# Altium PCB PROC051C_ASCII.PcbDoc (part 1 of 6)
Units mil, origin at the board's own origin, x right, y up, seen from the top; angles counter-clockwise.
Board outline 3304.03 x 2647.77 mil, 6 copper layers (TOP, L2, L3, L4, L5, BOTTOM), stack 55.54 mil thick; 370 components, 273 nets, 1273 pads, 1381 vias.
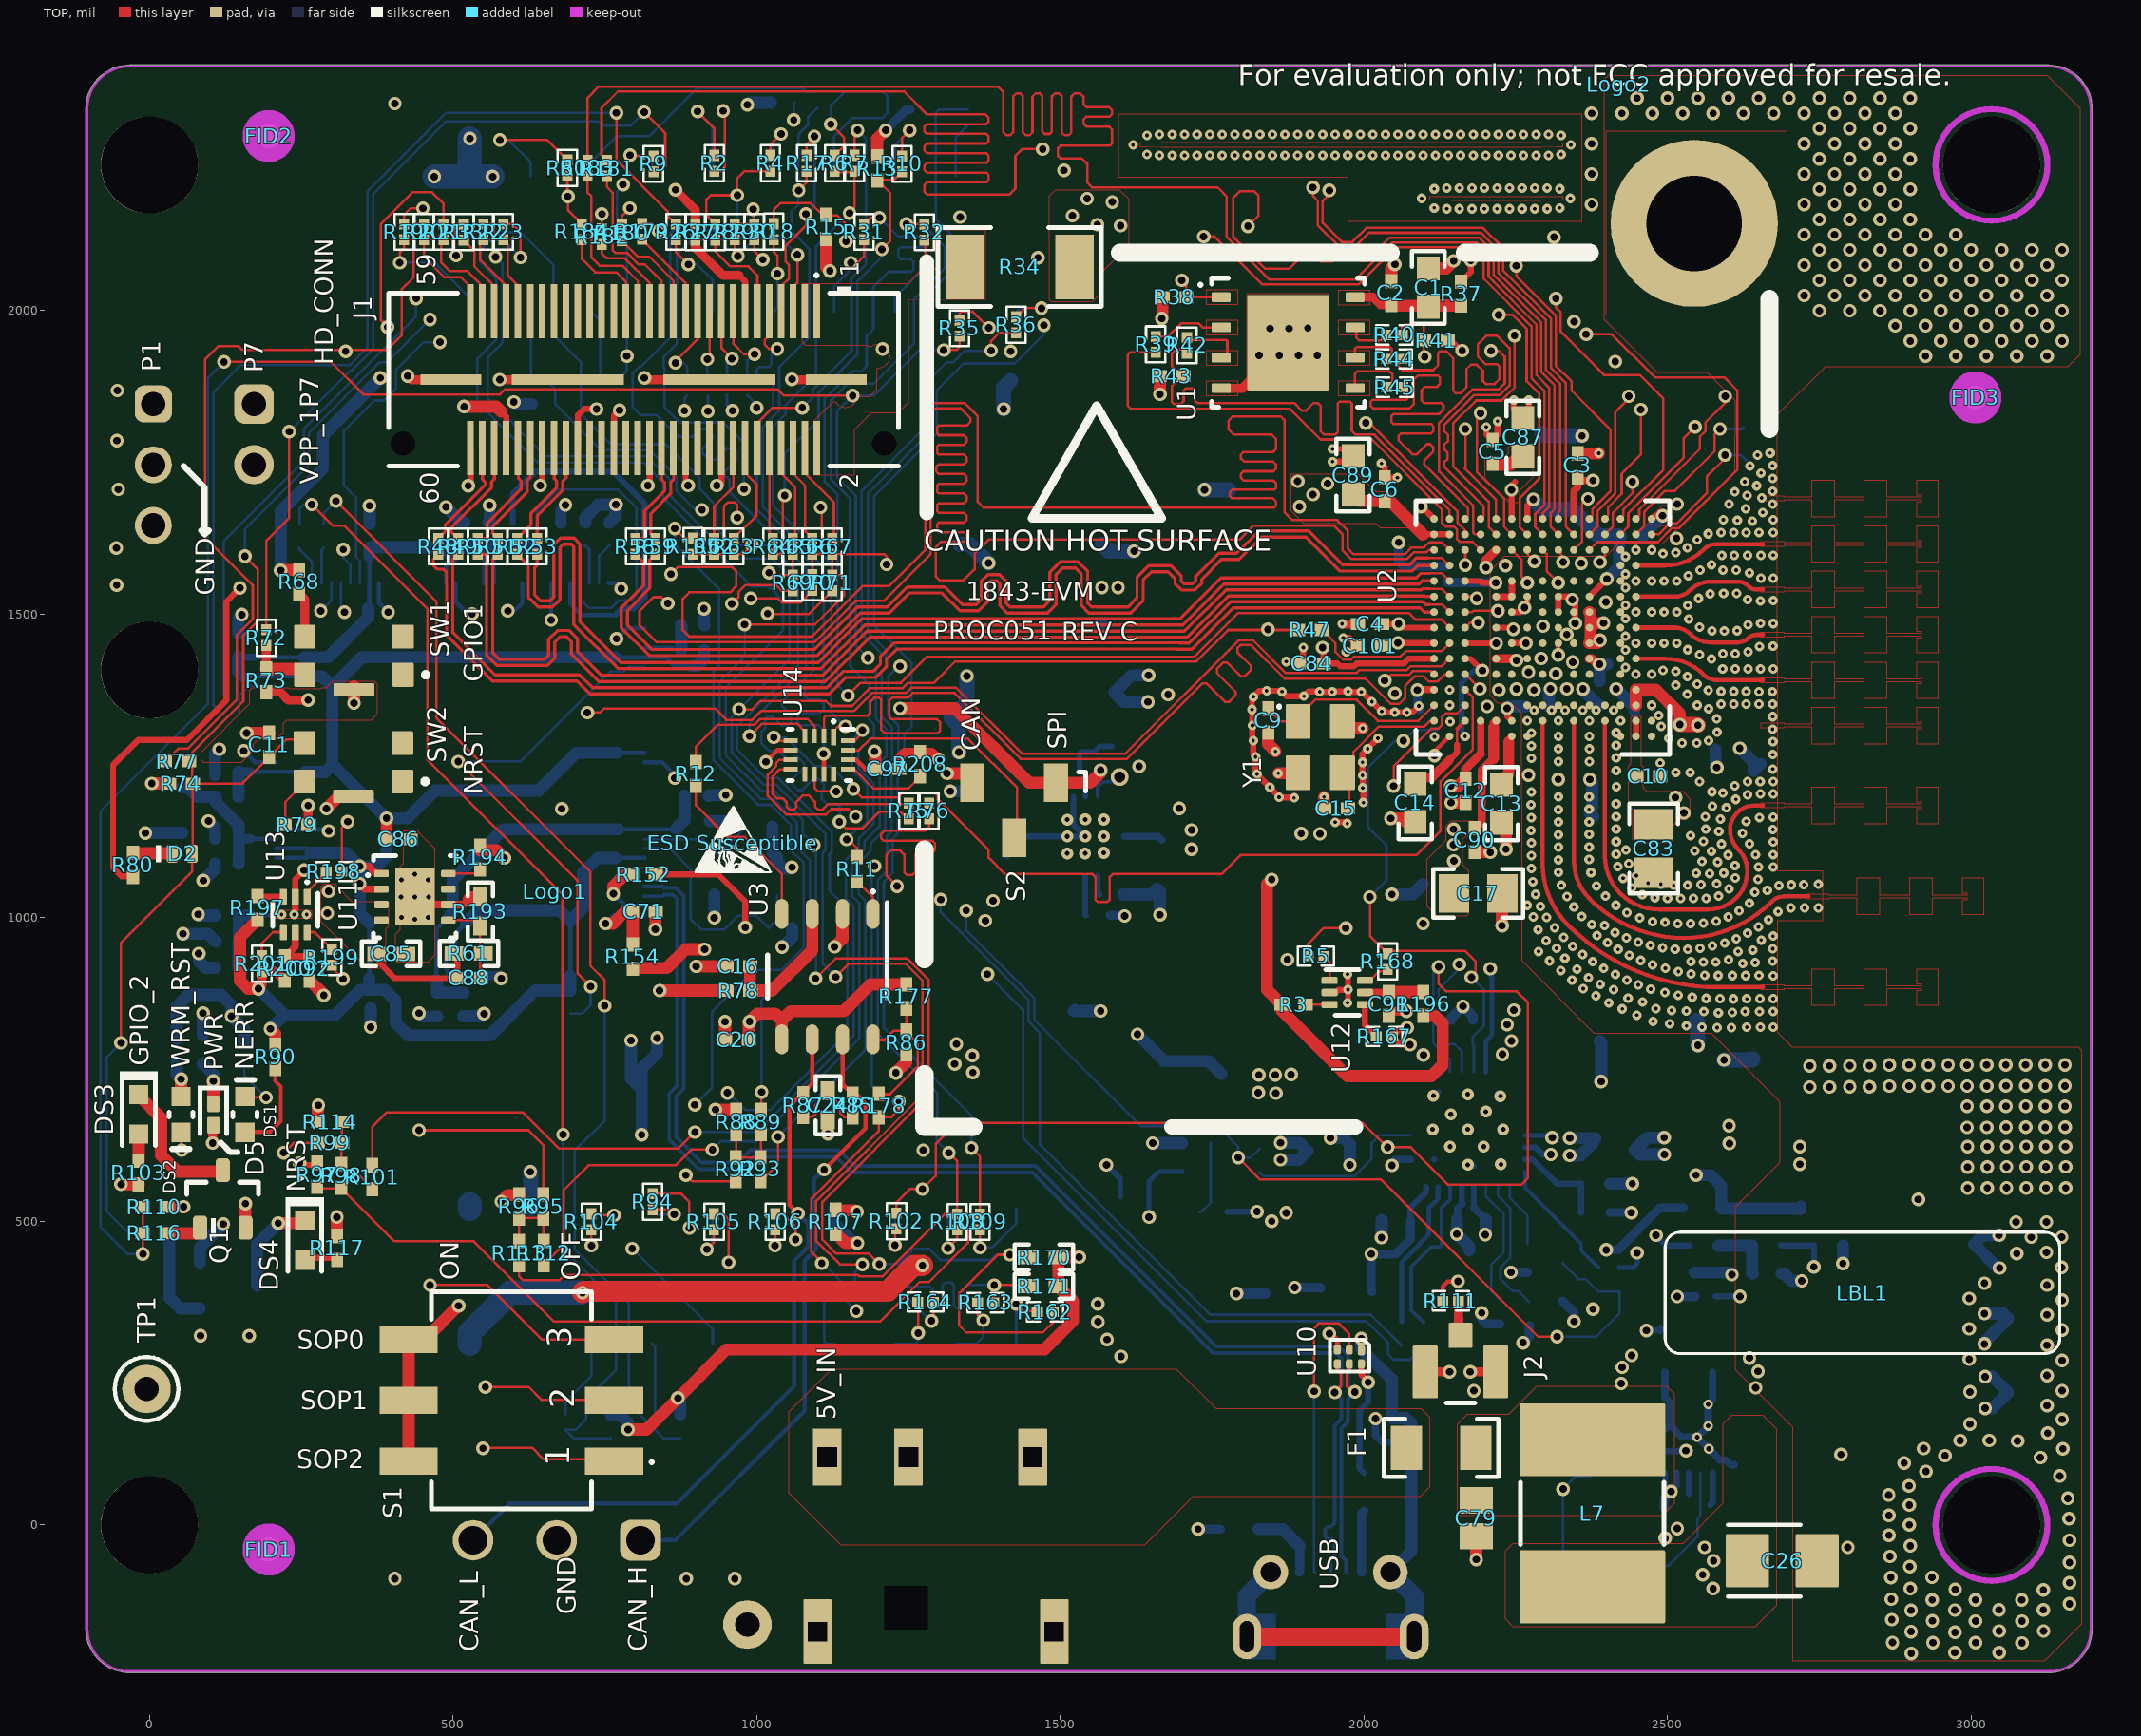
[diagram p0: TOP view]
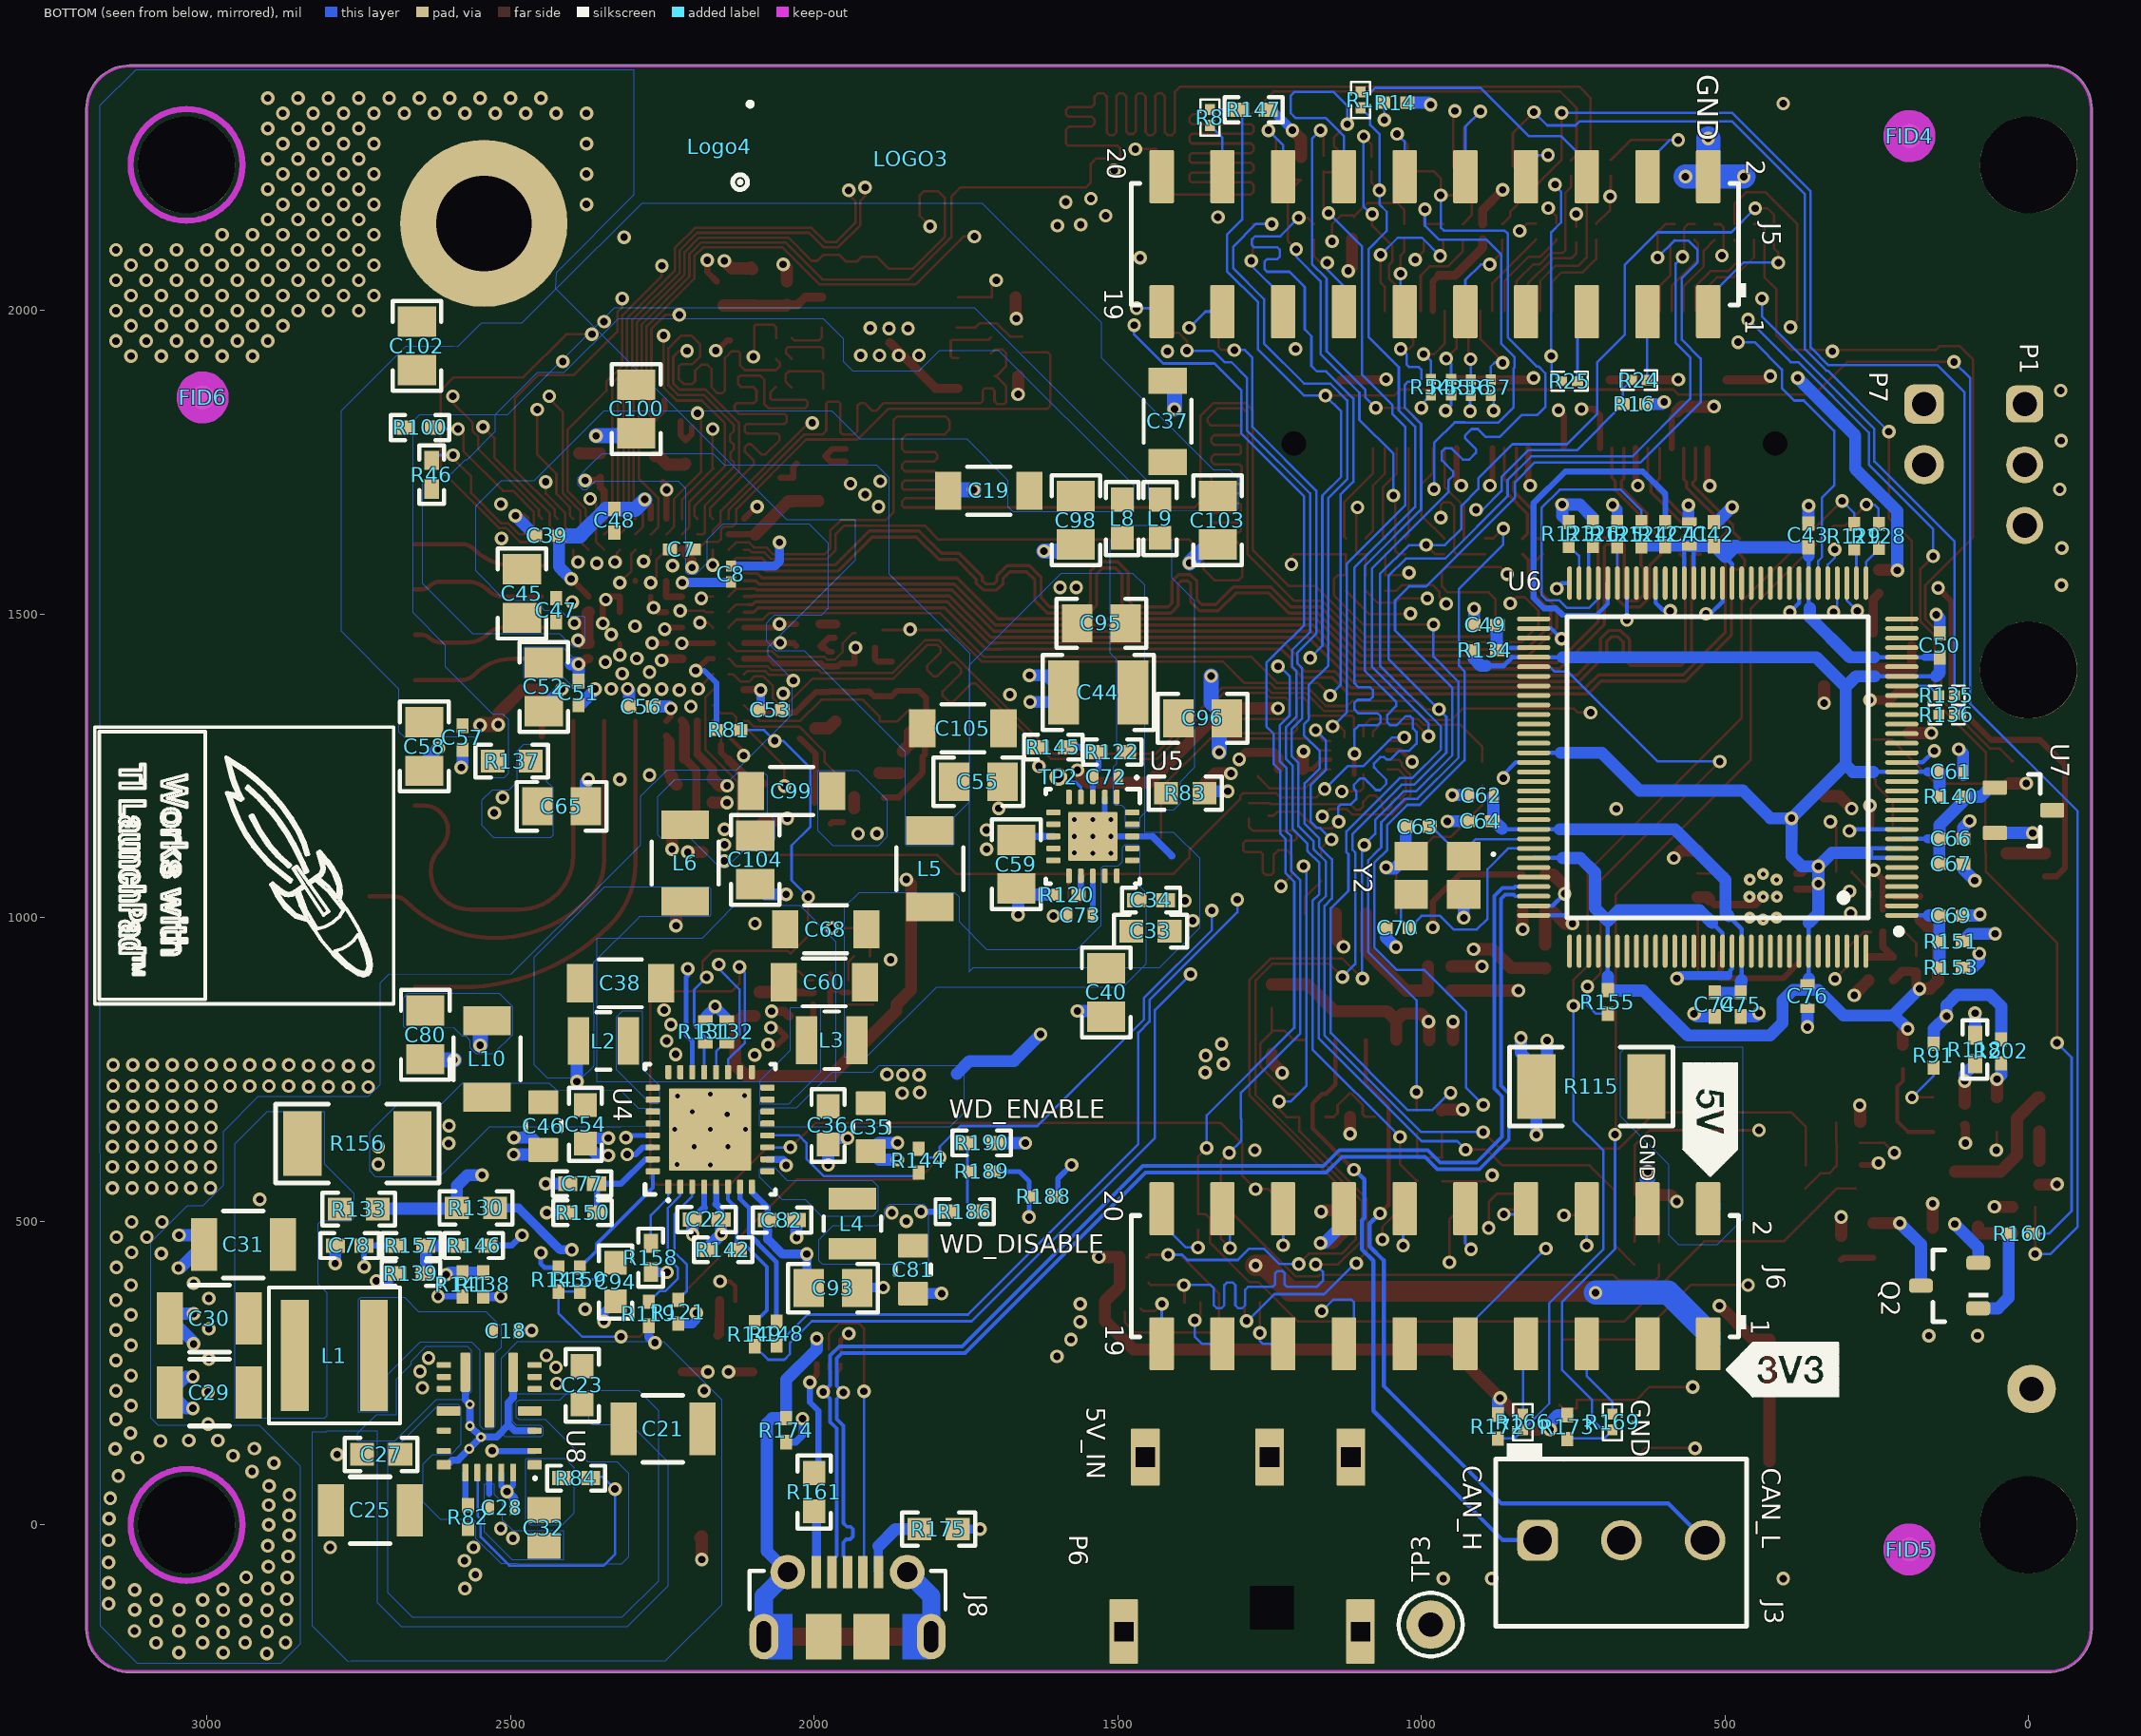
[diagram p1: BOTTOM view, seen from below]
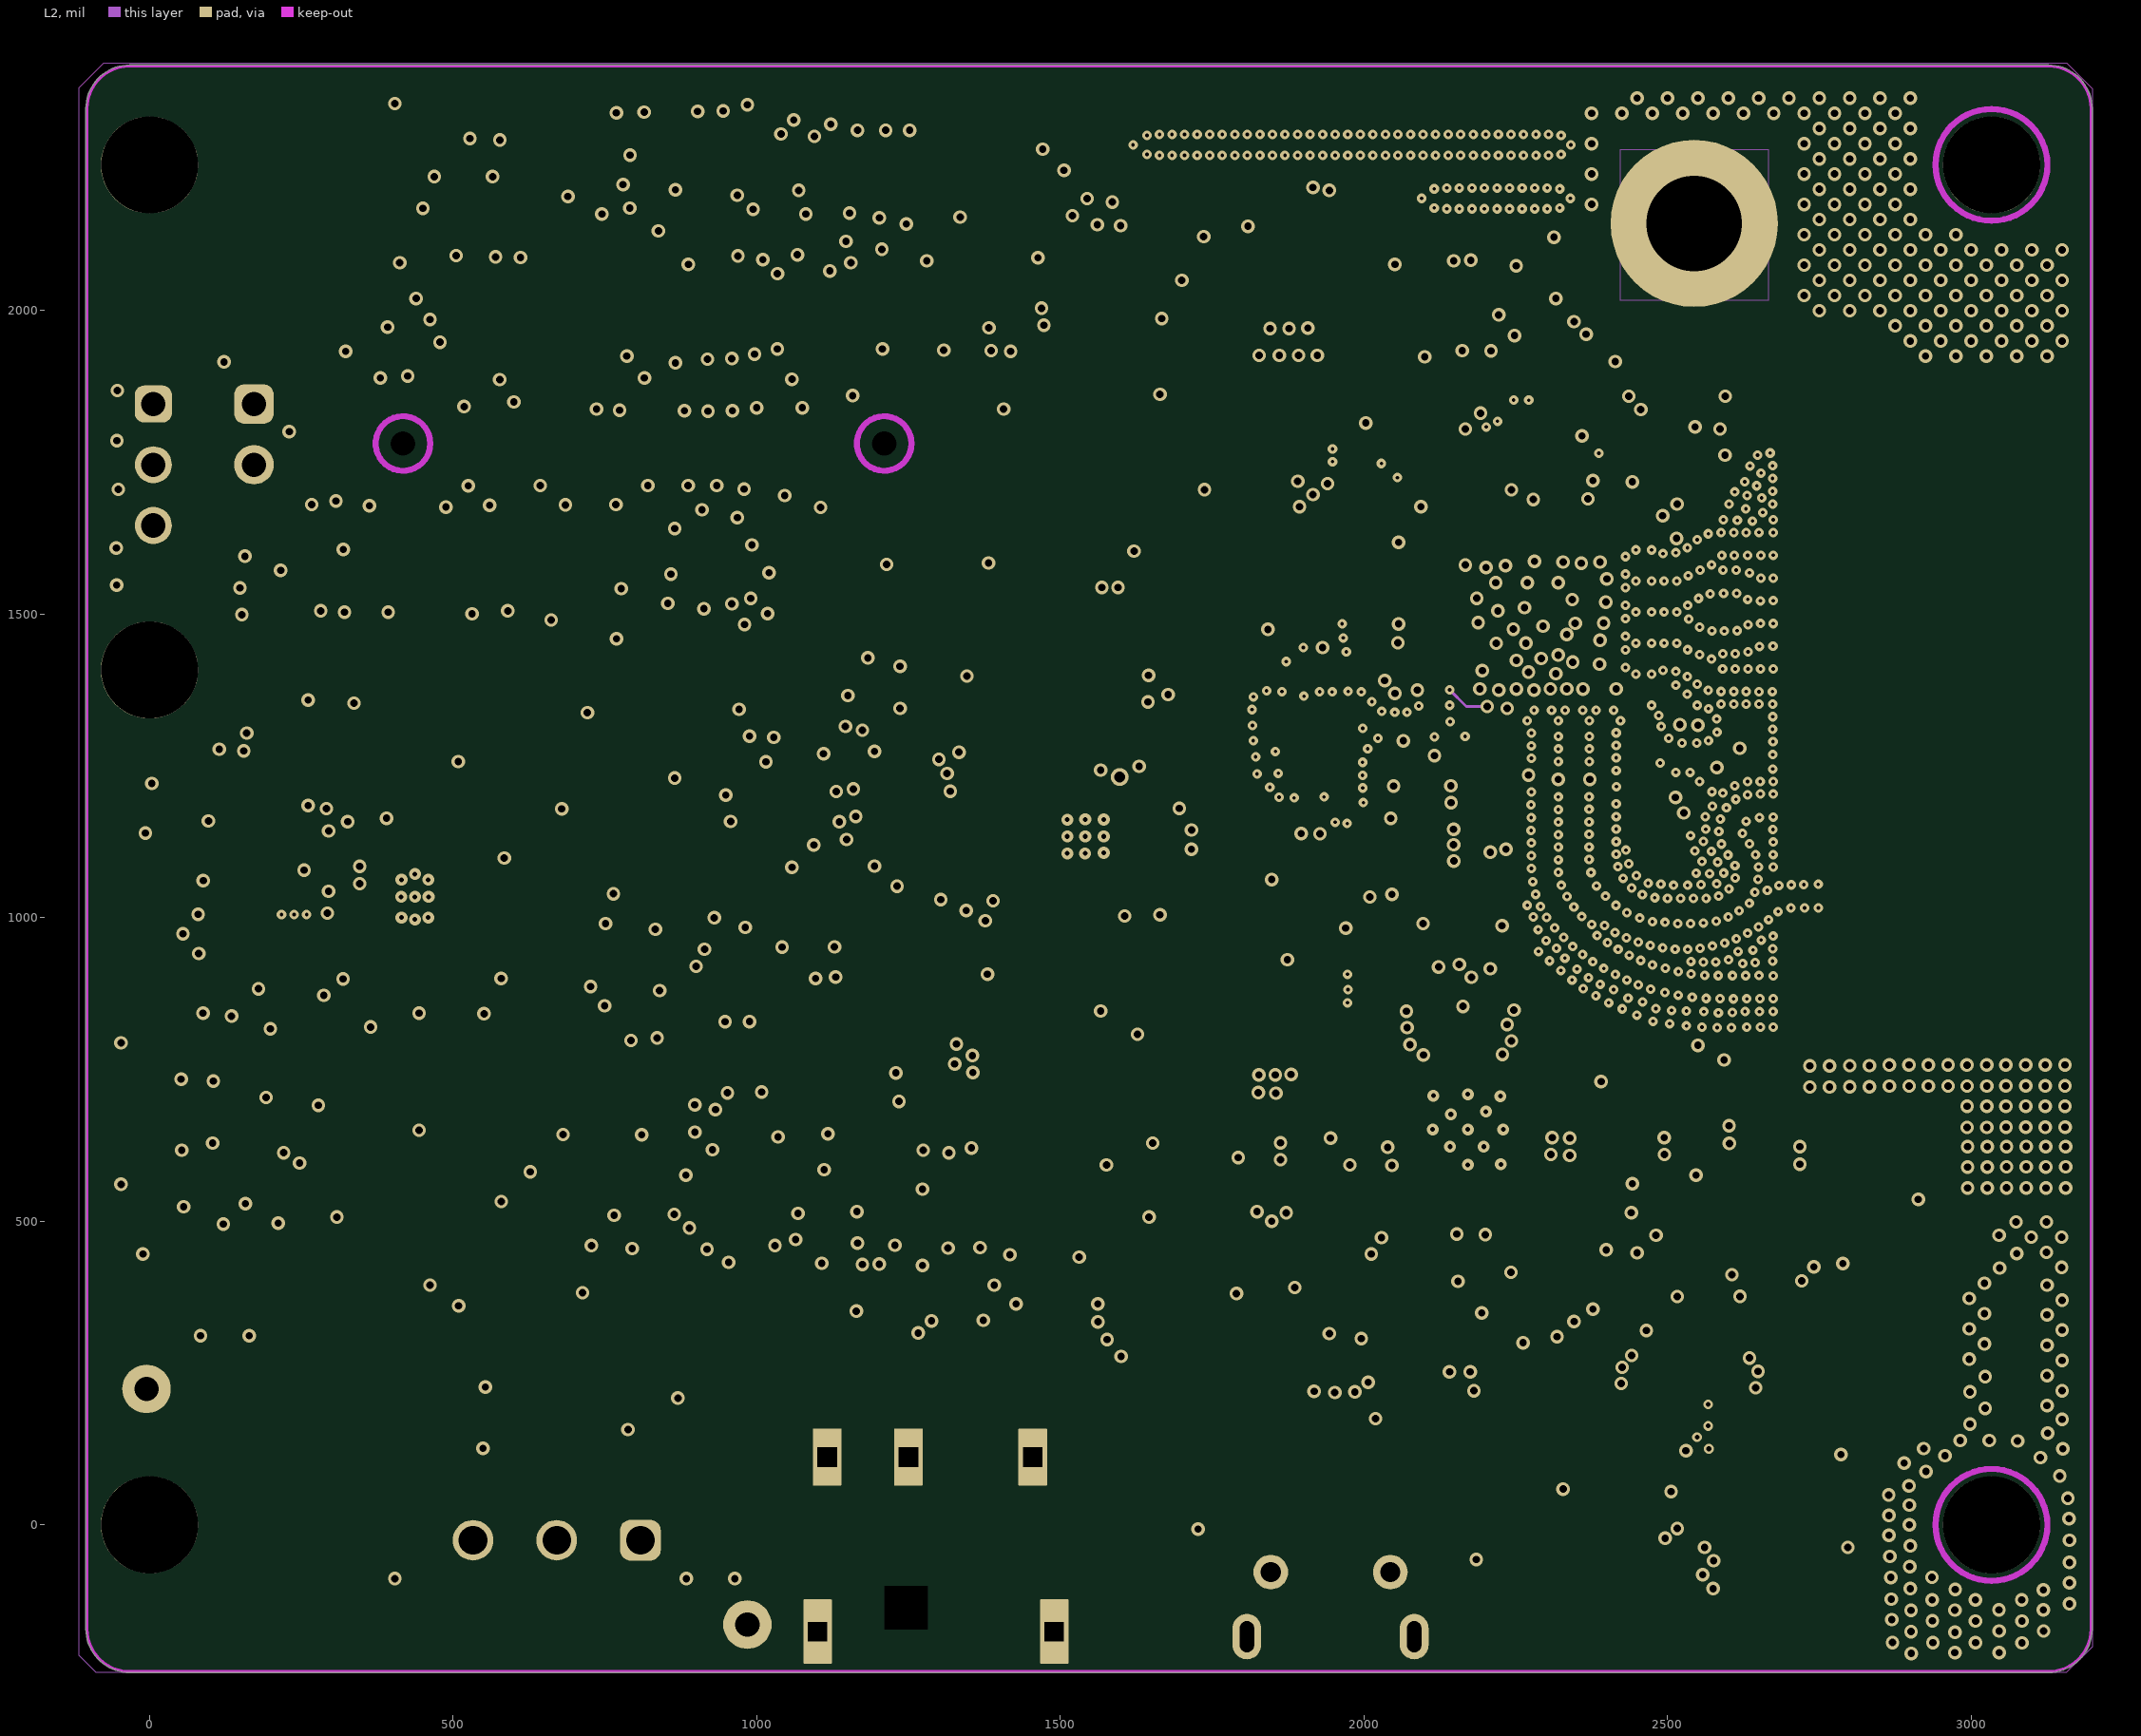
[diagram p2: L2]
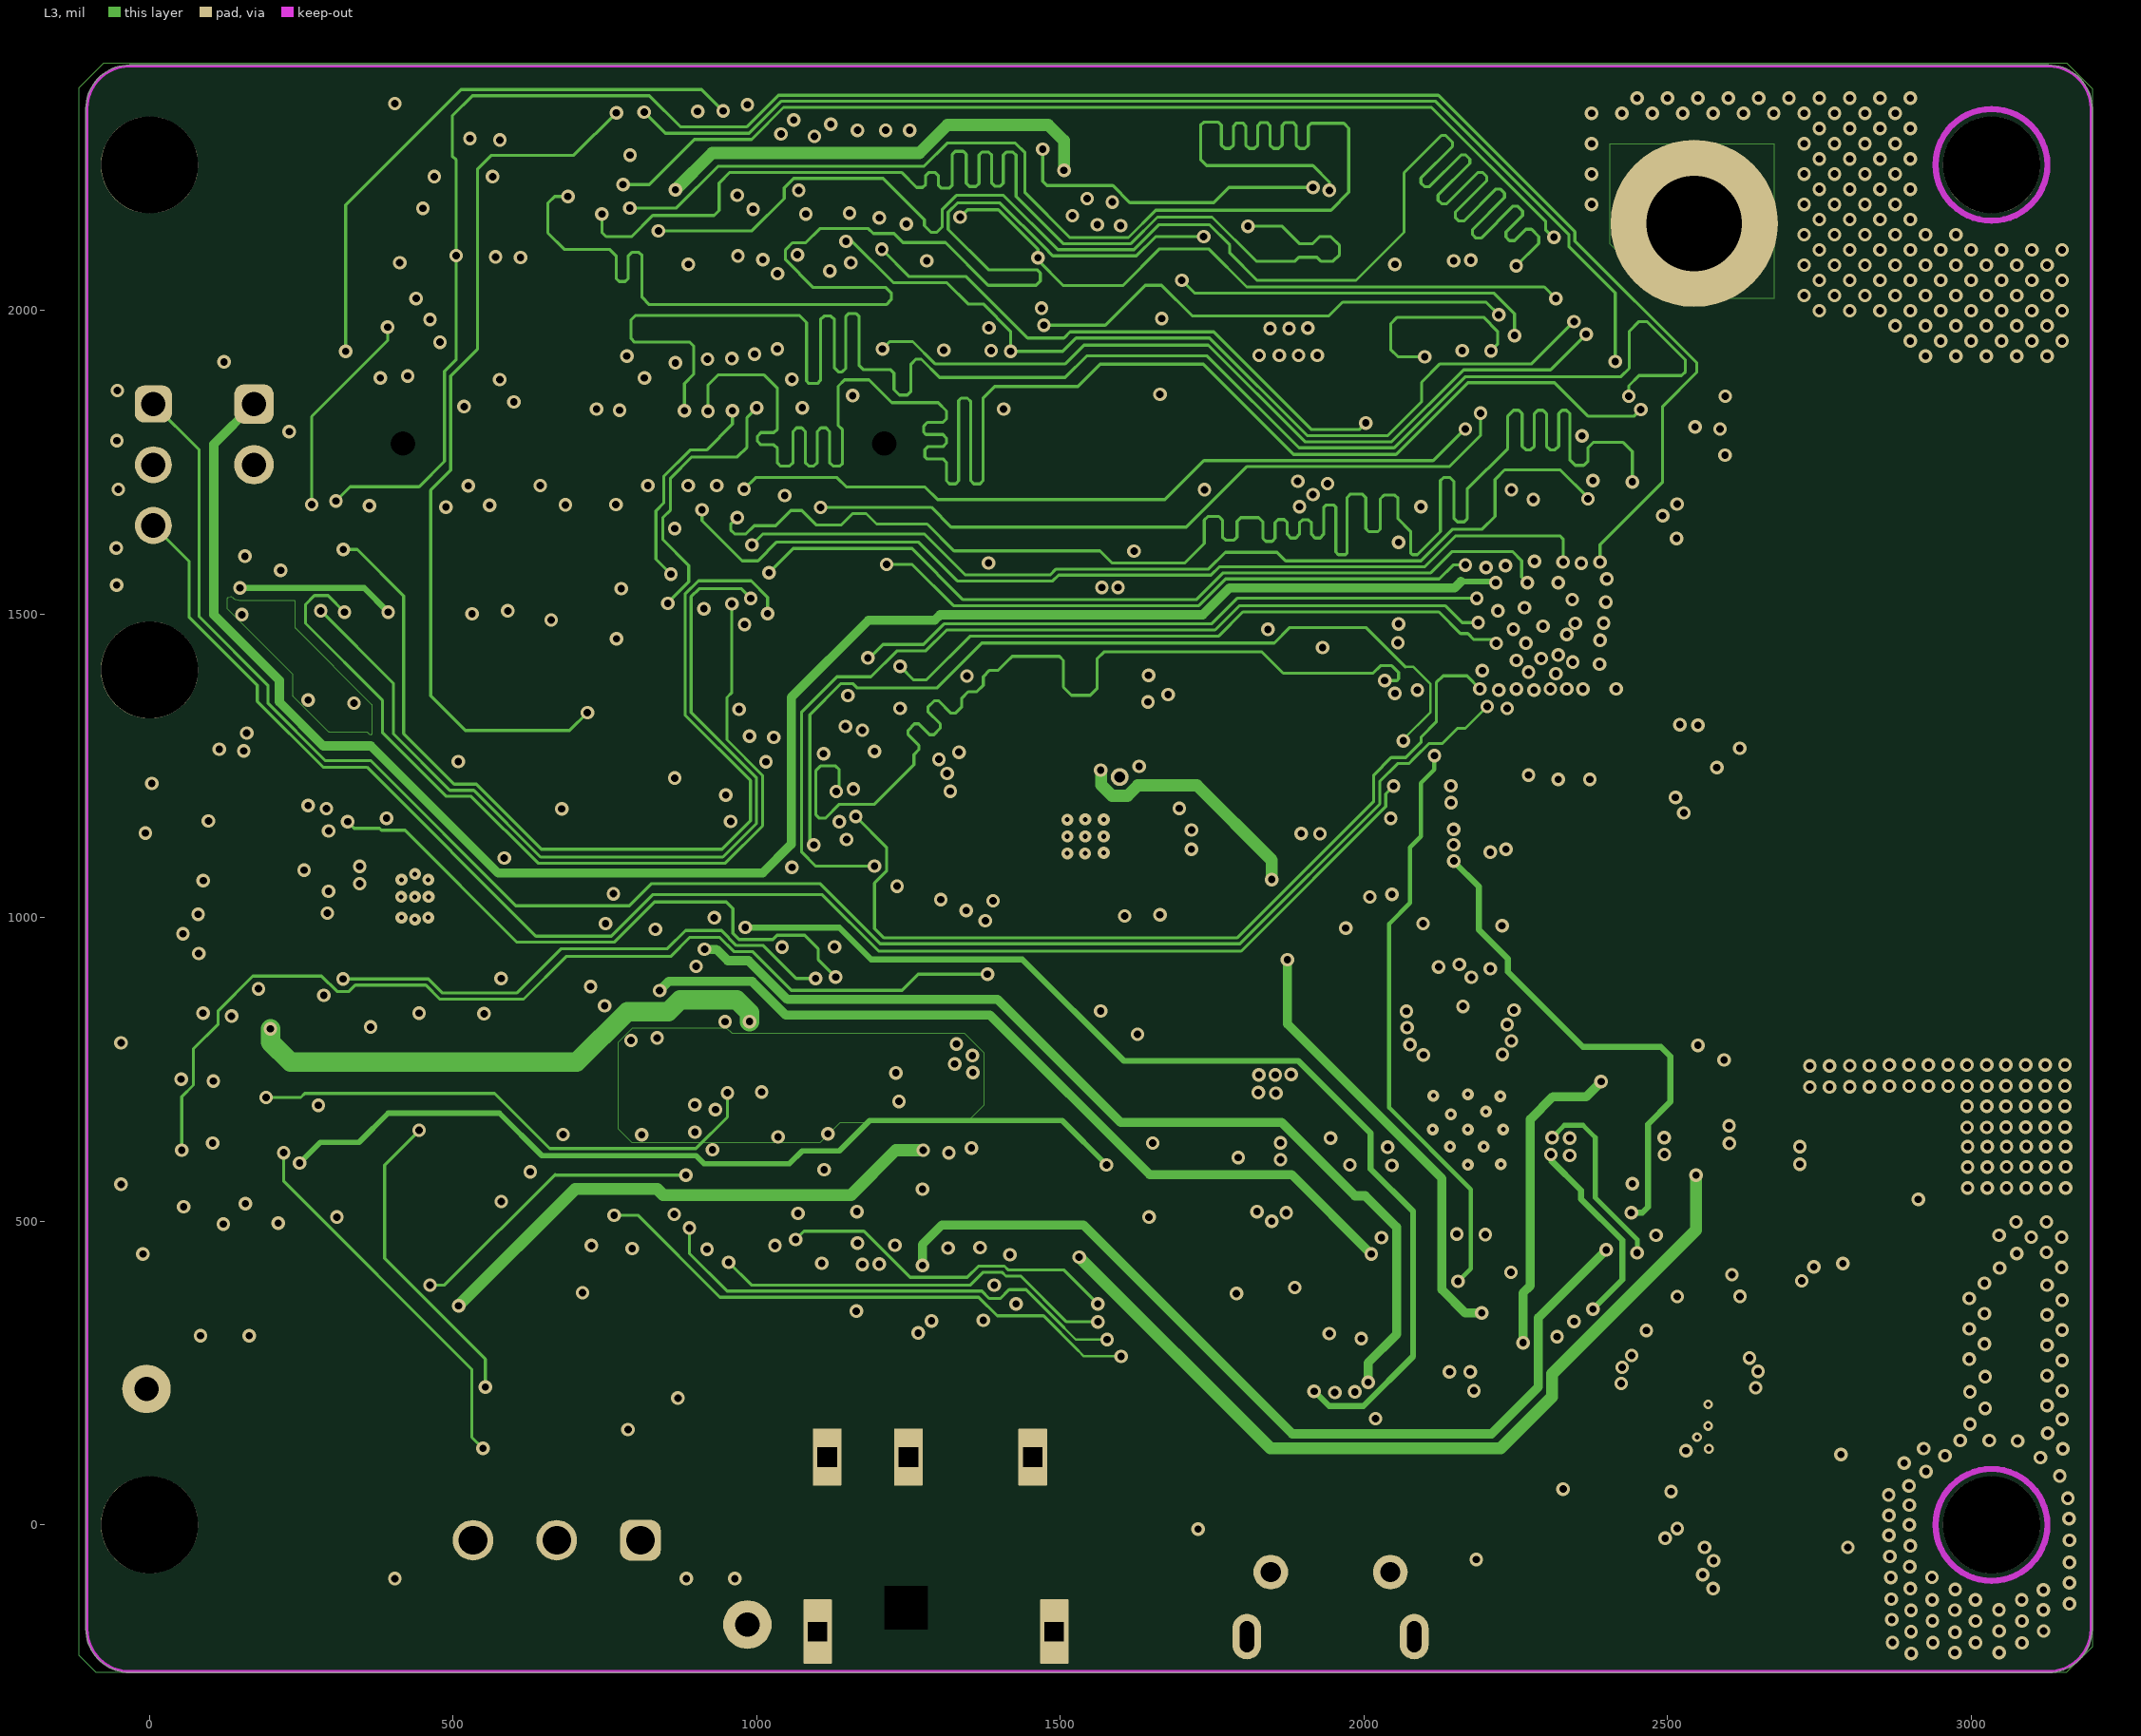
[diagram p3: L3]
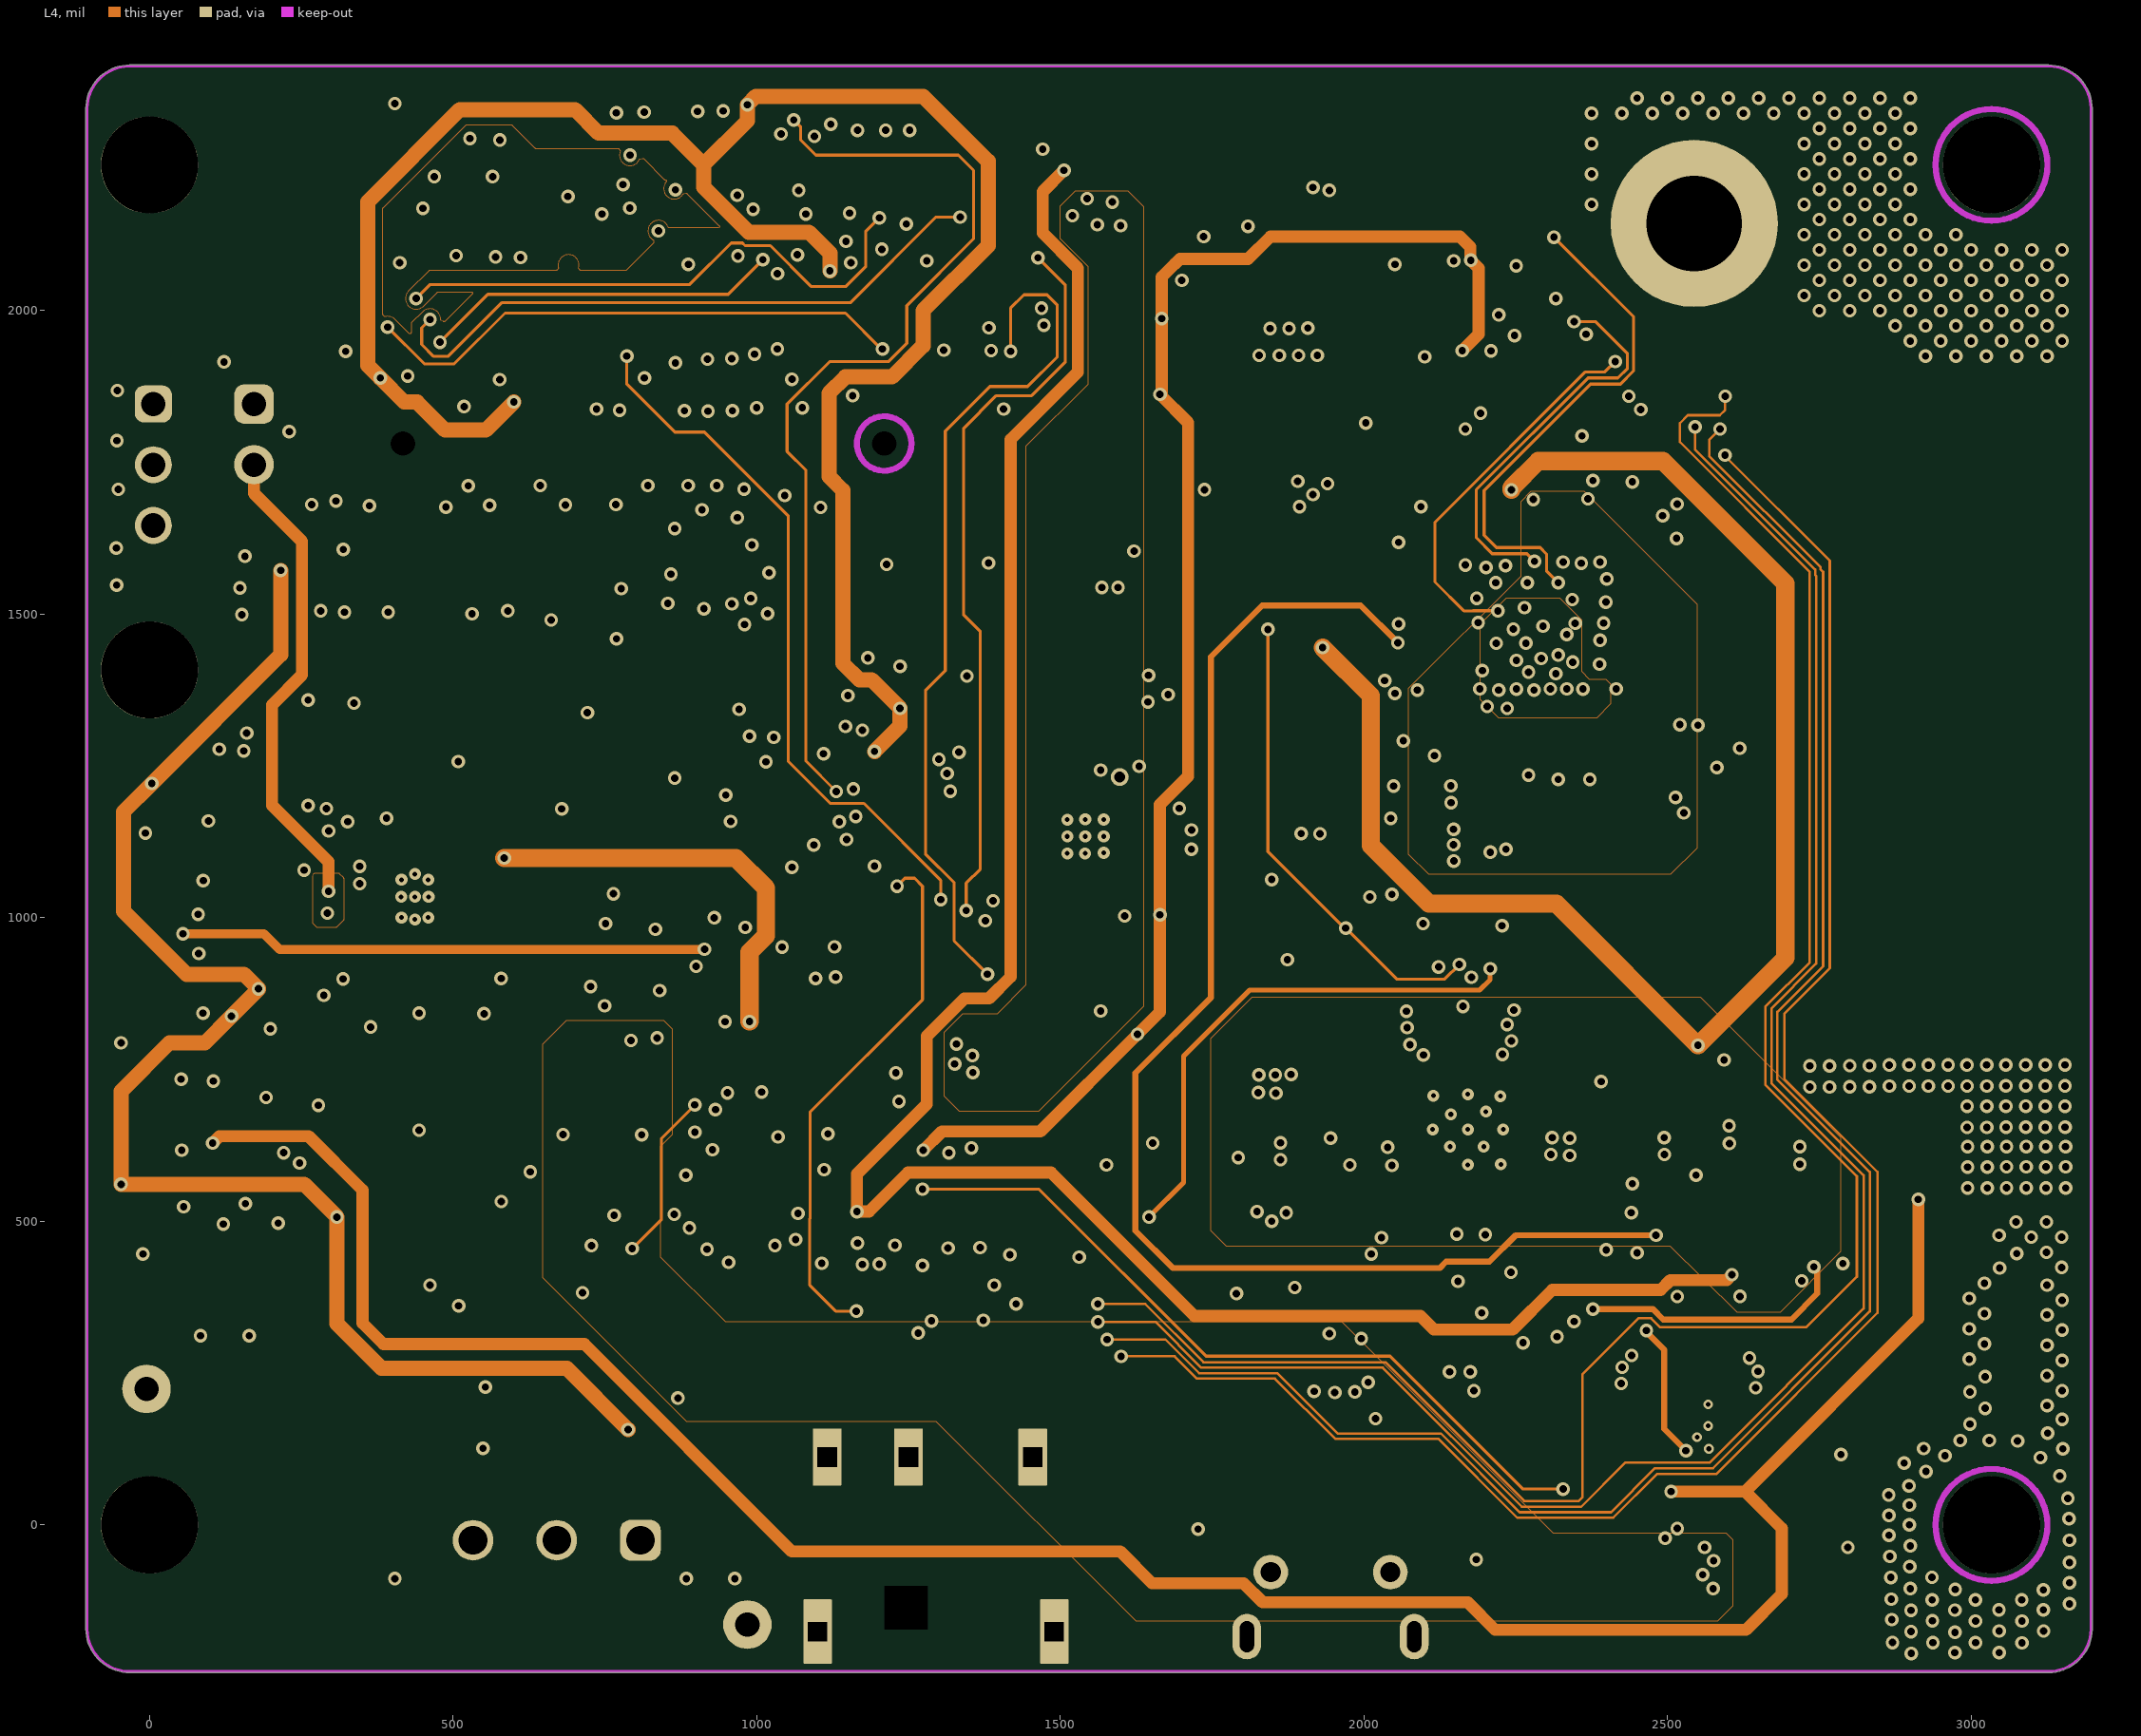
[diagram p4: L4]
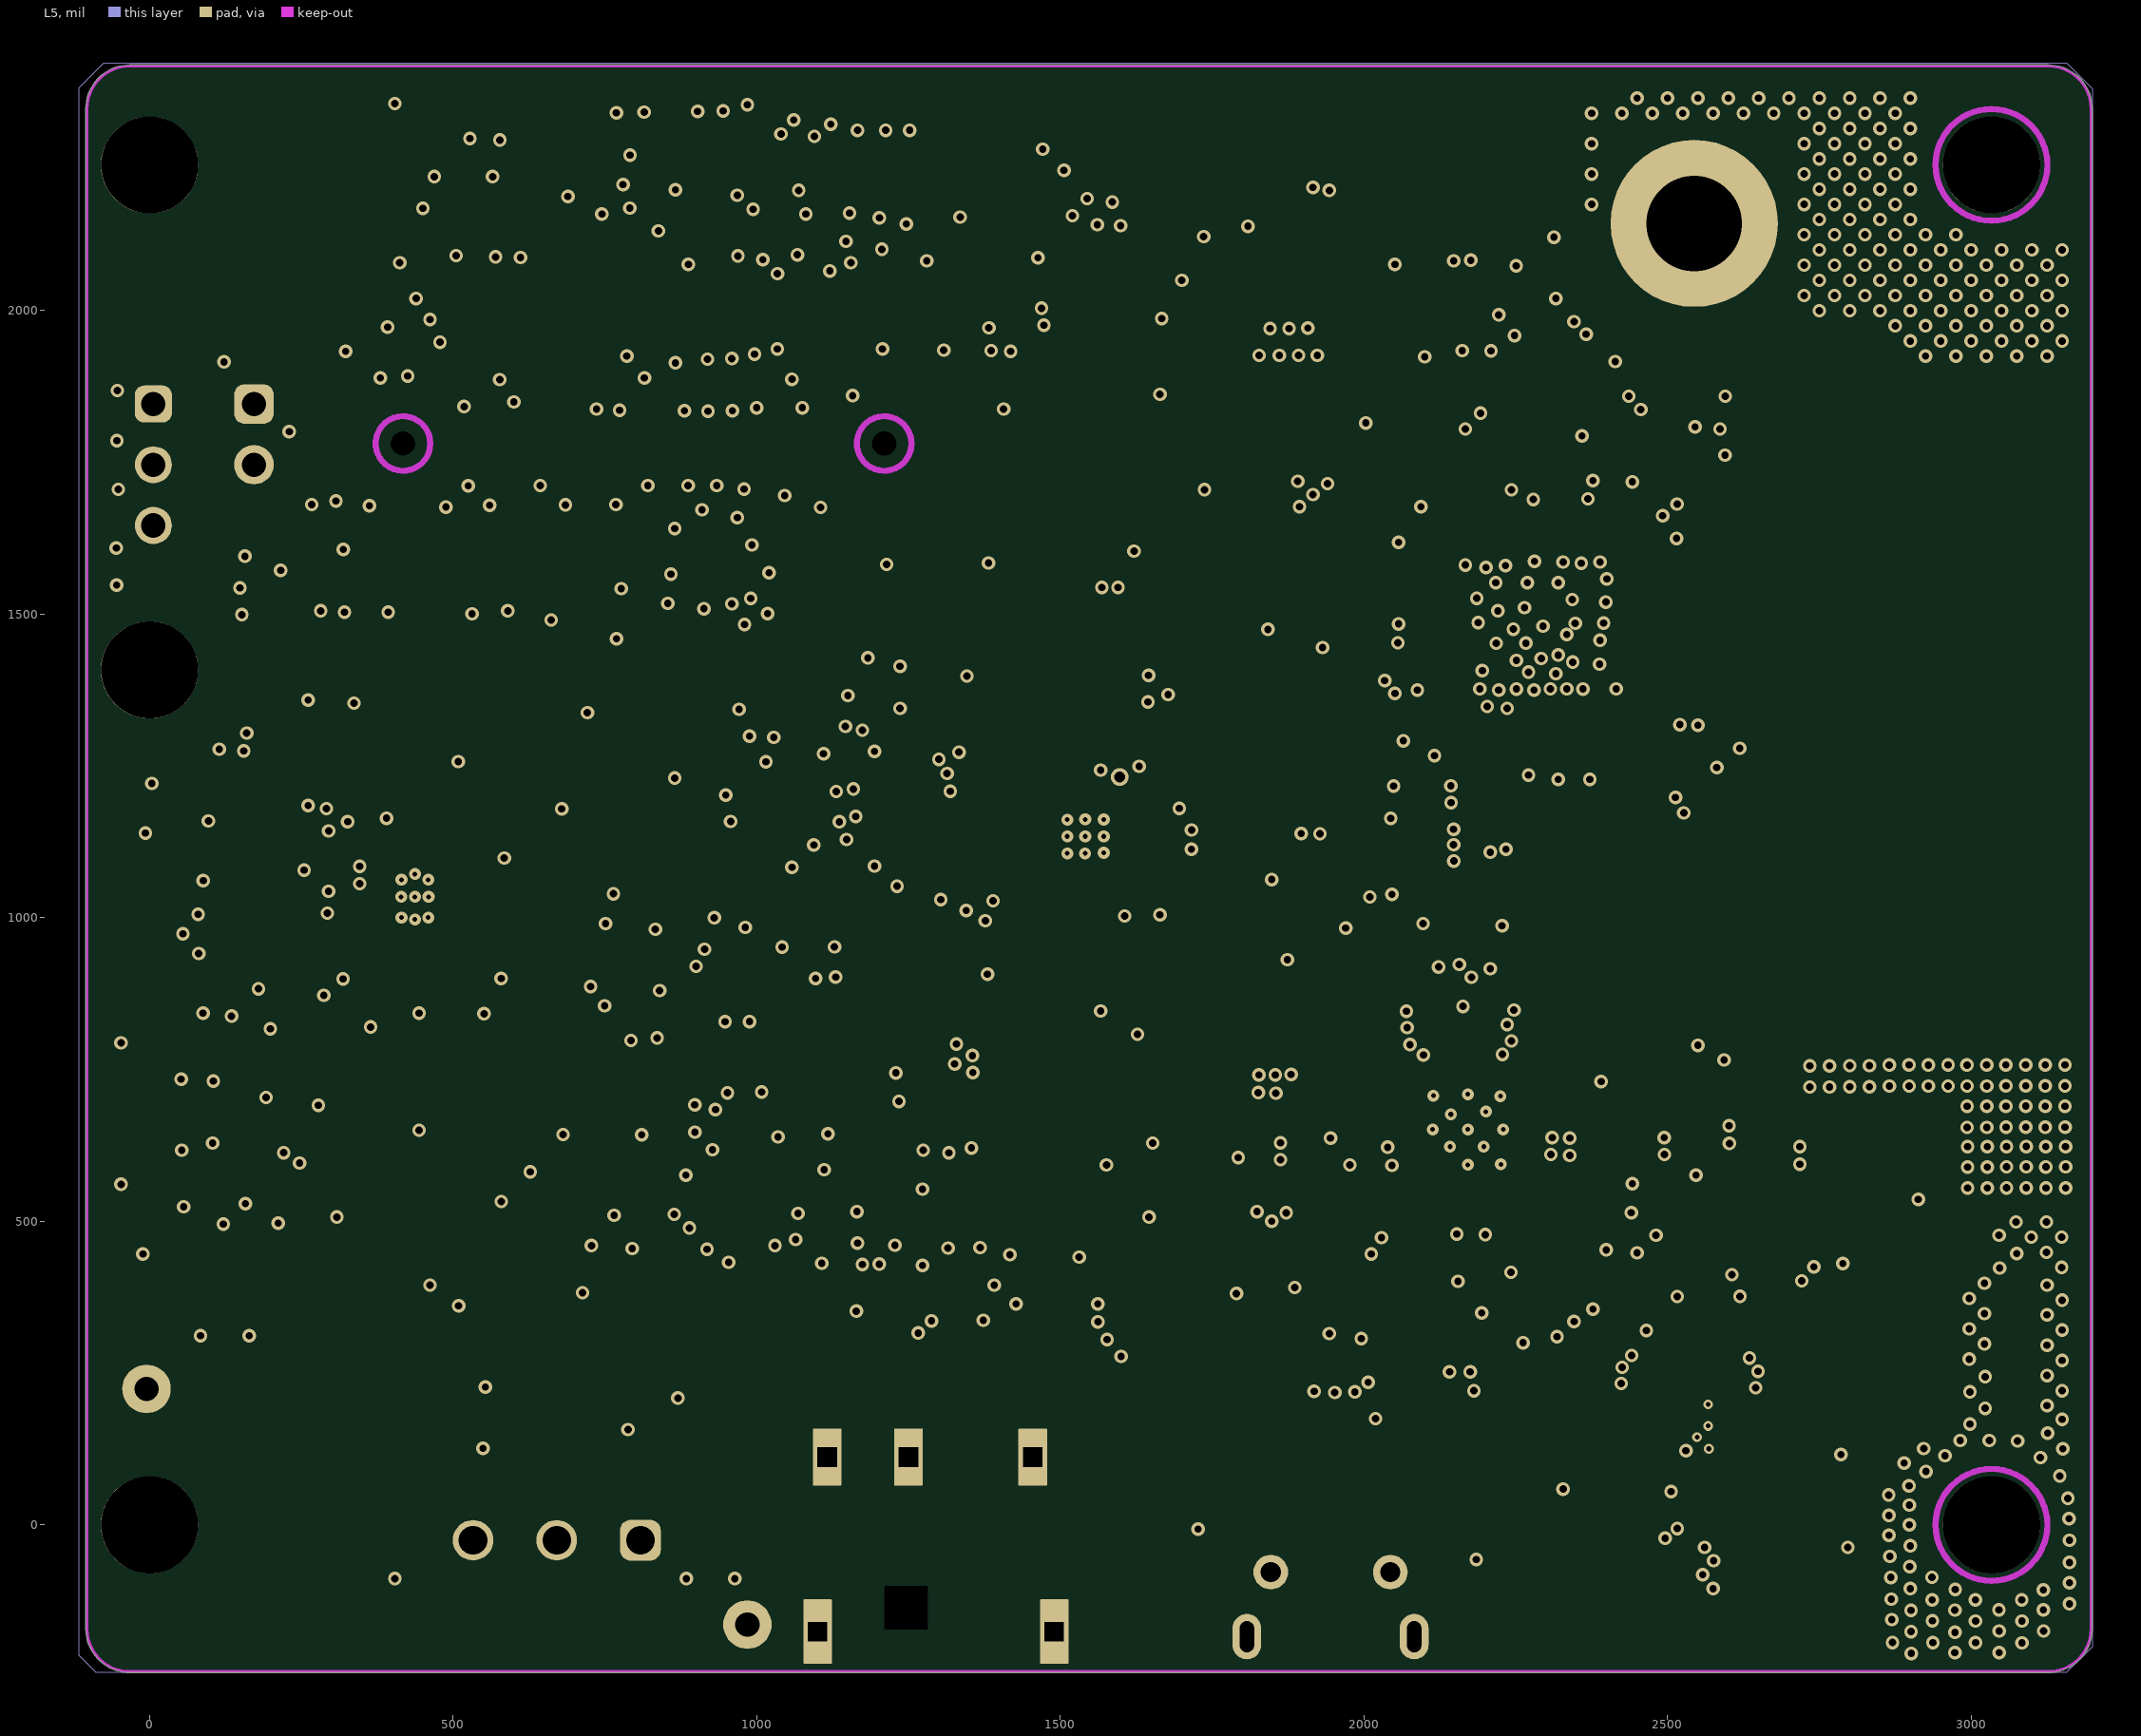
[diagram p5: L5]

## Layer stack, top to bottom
Top Solder: solder mask 0.8, Solder Resist, Dk 3.5
TOP: signal copper 1.6
Dielectric1: core 4, Rogers 4835, Dk 3.66
L2: signal copper 1.2
Dielectric2: prepreg 5.7, 370HR Prepreg 1080, Dk 3.9
L3: signal copper 1.2
Dielectric3: core 28, 370HR Prepreg 1080, Dk 4.36
L4: signal copper 1.2
Dielectric4: prepreg 5.84, 370HR Prepreg 1080, Dk 3.9
L5: signal copper 1.2
Dielectric5: core 4, 370HR Prepreg 1080, Dk 4.26
BOTTOM: signal copper 1.6
Bottom Solder: solder mask 0.8, Solder Resist, Dk 3.5

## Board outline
-104.76,-171.12 cw(c-102.75,-171) -104.76,-171 -104.76,2331.5 cw(c-102.75,2331.5) -104.7,2332 cw(c-102.75,2332.5) -104.76,2332.5 cw(c-32.75,2332.5) -32.75,2404.52 3127.25,2404.52 cw(c3127.25,2332.5) 3199.27,2332.5 3199.27,-172 cw(c3197.25,-172) 3199.26,-172.15 cw(c3127.25,-171.24) 3127.25,-243.26 -32.75,-243.26 cw(c-32.75,-171.24) -104.76,-171.24 cw(c-102.75,-171.24)

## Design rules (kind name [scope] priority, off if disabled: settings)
AssemblyTestPointUsage [All] p0: scope1count=1 scope1_0_kind=Board scope1_0_value=Board scope2count=1 scope2_0_kind=Board scope2_0_value=Board commentlength=0
AssemblyTestpoint [All] p0: scope1count=1 scope1_0_kind=Board scope1_0_value=Board scope2count=1 scope2_0_kind=Board scope2_0_value=Board commentlength=0
Clearance Clearance_L34 [All] p0 off: scope1count=1 scope1_0_kind=Board scope1_0_value=Board scope2count=1 scope2_0_kind=Board scope2_0_value=Board commentlength=60 gap=15 // Protel DXP Scope 1 Expression Was: InLayerClass('L3_L4')
Clearance Clearance_PMIC [All] p0 off: scope1count=1 scope1_0_kind=Board scope1_0_value=Board scope2count=1 scope2_0_kind=Board scope2_0_value=Board commentlength=70 gap=5 // Protel DXP Scope 1 Expression Was: WithinRoom('Copper to PMIC IC')
Clearance Clearance_BTM [All] p0: scope1count=1 scope1_0_kind=Layer scope1_0_value=BOTTOM scope2count=1 scope2_0_kind=Board scope2_0_value=Board commentlength=0 gap=15
Clearance Clearance_L25 [All] p0 off: scope1count=1 scope1_0_kind=Board scope1_0_value=Board scope2count=1 scope2_0_kind=Board scope2_0_value=Board commentlength=60 gap=15 // Protel DXP Scope 1 Expression Was: InLayerClass('L2_L5')
Clearance RX_TX_L34 [All] p0 off: scope1count=1 scope1_0_kind=Board scope1_0_value=Board scope2count=1 scope2_0_kind=NetClass scope2_0_value=RX_TX commentlength=60 gap=10 // Protel DXP Scope 1 Expression Was: InLayerClass('L3_L4')
Clearance COPLANNER [All] p0 off: scope1count=1 scope1_0_kind=Board scope1_0_value=Board scope2count=1 scope2_0_kind=Board scope2_0_value=Board commentlength=59 gap=3 // Protel DXP Scope 1 Expression Was: WithinRoom('COUPLE')
Clearance Clearance_1 [All] p0 off: scope1count=1 scope1_0_kind=Board scope1_0_value=Board scope2count=1 scope2_0_kind=Board scope2_0_value=Board commentlength=69 gap=6.71 // Protel DXP Scope 1 Expression Was: WithinRoom('DUT') OR InPolygon
Clearance Clearance_TOP [All] p0: scope1count=1 scope1_0_kind=Layer scope1_0_value=TOP scope2count=1 scope2_0_kind=Board scope2_0_value=Board commentlength=0 gap=10
Clearance RX_TX_L25 [All] p0 off: scope1count=1 scope1_0_kind=Board scope1_0_value=Board scope2count=1 scope2_0_kind=NetClass scope2_0_value=RX_TX commentlength=60 gap=10 // Protel DXP Scope 1 Expression Was: InLayerClass('L2_L5')
Clearance RX_TX_TOP [All] p0: scope1count=1 scope1_0_kind=Layer scope1_0_value=TOP scope2count=1 scope2_0_kind=NetClass scope2_0_value=RX_TX commentlength=0 gap=10
Clearance same_net_cl_inner [All] p0 off: scope1count=1 scope1_0_kind=Board scope1_0_value=Board scope2count=1 scope2_0_kind=Board scope2_0_value=Board commentlength=61 gap=10 // Protel DXP Scope 1 Expression Was: InLayerClass('layers')
Clearance Clearance_L34 [InLayerClass('L3_L4')] p1: gap=15 ignorepadtopadclearanceinfootprint=FALSE except(0: Arc-Hole Track-Hole SMDPad-Hole THPad-Hole Via-Hole Fill-Hole Poly-Hole Region-Hole Text-Hole; 5: Arc-Track Arc-SMDPad Track-Track Track-SMDPad; 5.9: Via-Via; 6: Arc-Arc Arc-THPad Arc-Via Track-THPad Track-Via SMDPad-SMDPad SMDPad-THPad SMDPad-Via SMDPad-Fill SMDPad-Poly THPad-THPad THPad-Via Via-Fill Via-Poly; 10: THPad-Fill THPad-Poly)
Clearance Clearance_PMIC [WithinRoom('Copper to PMIC IC')] p2: gap=5 ignorepadtopadclearanceinfootprint=FALSE except(0: Arc-Hole Track-Hole SMDPad-Hole THPad-Hole Via-Hole Fill-Hole Poly-Hole Region-Hole Text-Hole; 4: Arc-Track Track-Track; 4.5: Track-Via SMDPad-SMDPad)
Clearance Clearance_BTM [OnLayer('BOTTOM')] p3: gap=15 ignorepadtopadclearanceinfootprint=FALSE except(0: Arc-SMDPad Arc-Hole Track-Hole SMDPad-Hole THPad-Hole Via-Hole Fill-Hole Poly-Hole Region-Hole Text-Hole; 4: Track-SMDPad; 4.5: Arc-Via Track-Via; 5: Arc-Arc Arc-Track Track-Track SMDPad-Via; 6: Arc-THPad Track-THPad SMDPad-SMDPad SMDPad-THPad THPad-THPad THPad-Via; 8: Arc-Fill Arc-Poly Track-Fill Track-Poly Via-Fill Via-Poly; 9: SMDPad-Fill SMDPad-Poly THPad-Fill THPad-Poly; 16.6: Via-Via)
Clearance Clearance_L25 [InLayerClass('L2_L5')] p4: gap=15 ignorepadtopadclearanceinfootprint=FALSE except(0: Arc-Hole Track-Hole SMDPad-Hole THPad-Hole Via-Hole Fill-Hole Poly-Hole Region-Hole Text-Hole; 5: Arc-Track Arc-SMDPad Track-Track Track-SMDPad; 6: Arc-Arc Arc-THPad Arc-Via Track-THPad Track-Via SMDPad-SMDPad SMDPad-THPad SMDPad-Via SMDPad-Fill SMDPad-Poly THPad-THPad THPad-Via Via-Via Via-Fill Via-Poly; 10: THPad-Fill THPad-Poly)
Clearance RX_TX_L34 [InLayerClass('L3_L4') vs InNetClass('RX_TX')] p5: gap=10 ignorepadtopadclearanceinfootprint=FALSE except(0: Arc-Hole Track-Hole SMDPad-Hole THPad-Hole Via-Hole Fill-Hole Poly-Hole Region-Hole Text-Hole; 4.86: Via-Via; 5: Arc-SMDPad Track-SMDPad; 6: Arc-Arc Arc-Track Arc-THPad Arc-Via Track-Track Track-THPad Track-Via SMDPad-SMDPad SMDPad-THPad SMDPad-Via SMDPad-Fill SMDPad-Poly THPad-THPad THPad-Via Via-Fill Via-Poly; 15: Arc-Fill Arc-Poly Track-Poly Fill-Fill Fill-Poly Poly-Poly; 16: Track-Fill)
Clearance COPLANNER [WithinRoom('COUPLE')] p6: gap=3 ignorepadtopadclearanceinfootprint=FALSE except(0: Arc-Hole Track-Hole SMDPad-Hole THPad-Hole Via-Hole Fill-Hole Poly-Hole Region-Hole Text-Hole)
Clearance Clearance_1 [WithinRoom('DUT') OR InPolygon] p7: gap=6.71 ignorepadtopadclearanceinfootprint=FALSE except(0: Arc-Hole Track-Hole SMDPad-Hole THPad-Hole Via-Hole Fill-Hole Poly-Hole Region-Hole Text-Hole; 4: Track-Track Track-SMDPad Track-Via SMDPad-Via; 6.6: Via-Region; 6.72: Arc-Region Arc-Text Track-Region Track-Text SMDPad-Region SMDPad-Text THPad-Region THPad-Text Via-Text Fill-Region Fill-Text Poly-Region Poly-Text Region-Region Region-Text Text-Text; 9: SMDPad-Poly; 10: THPad-Poly)
Clearance Clearance_TOP [OnLayer('TOP')] p8: gap=10 ignorepadtopadclearanceinfootprint=FALSE except(0: Arc-SMDPad Arc-Hole Track-Hole SMDPad-Hole THPad-Hole Via-Hole Fill-Hole Poly-Hole Region-Hole Text-Hole; 4: Arc-Arc Arc-Track Arc-Via Track-Track Track-SMDPad Track-Via; 5: SMDPad-SMDPad SMDPad-THPad SMDPad-Via; 6: Arc-THPad Track-THPad THPad-THPad THPad-Via Via-Fill Via-Poly; 8: Arc-Fill Arc-Poly Track-Fill Track-Poly; 9: SMDPad-Fill SMDPad-Poly THPad-Fill THPad-Poly; 15: Fill-Fill Fill-Poly Poly-Poly; 15.4: Via-Via)
Clearance RX_TX_L25 [InLayerClass('L2_L5') vs InNetClass('RX_TX')] p9: gap=10 ignorepadtopadclearanceinfootprint=FALSE except(0: Arc-Hole Track-Hole SMDPad-Hole THPad-Hole Via-Hole Fill-Hole Poly-Hole Region-Hole Text-Hole; 5: Arc-SMDPad Track-SMDPad; 6: Arc-Arc Arc-Track Arc-THPad Arc-Via Track-Track Track-THPad Track-Via SMDPad-SMDPad SMDPad-THPad SMDPad-Via SMDPad-Fill SMDPad-Poly THPad-THPad THPad-Via Via-Fill Via-Poly; 9.1: Via-Via; 15: Arc-Fill Arc-Poly Track-Fill Track-Poly Fill-Fill Fill-Poly Poly-Poly)
Clearance RX_TX_TOP [OnLayer('TOP') vs InNetClass('RX_TX')] p10: gap=10 ignorepadtopadclearanceinfootprint=FALSE except(0: Arc-Hole Track-Hole SMDPad-Hole THPad-Hole Via-Hole Fill-Hole Poly-Hole Region-Hole Text-Hole; 4: Arc-Track Arc-SMDPad Track-Track Track-SMDPad SMDPad-Via; 6: Arc-THPad Track-THPad SMDPad-SMDPad SMDPad-THPad THPad-THPad THPad-Via THPad-Fill THPad-Poly; 6.7: Arc-Fill Arc-Poly Track-Fill Track-Poly; 6.72: Arc-Via Track-Via Via-Fill Via-Poly; 9: SMDPad-Fill SMDPad-Poly; 15.4: Via-Via)
Clearance same_net_cl_inner [InLayerClass('layers')] p11: gap=10 ignorepadtopadclearanceinfootprint=FALSE except(0: Arc-Hole Track-Hole SMDPad-Hole THPad-Hole Via-Hole Fill-Hole Poly-Hole Region-Hole Text-Hole; 5: Arc-THPad Track-Track Track-SMDPad Track-THPad SMDPad-SMDPad SMDPad-THPad THPad-THPad; 6: Track-Via SMDPad-Via THPad-Via Via-Via Via-Fill Via-Poly; 15: Arc-Fill Arc-Poly Fill-Fill Fill-Poly Poly-Poly)
ComponentClearance [All] p0: scope1count=1 scope1_0_kind=Board scope1_0_value=Board scope2count=1 scope2_0_kind=Board scope2_0_value=Board commentlength=0 gap=10 collisioncheckmode=3
DiffPairsRouting Diff_100ohm [All] p0 off: scope1count=1 scope1_0_kind=Board scope1_0_value=Board scope2count=1 scope2_0_kind=Board scope2_0_value=Board commentlength=73 // Protel DXP Scope 1 Expression Was: InDifferentialPairClass('100_OHM')
DiffPairsRouting Diff_90ohm [All] p0 off: scope1count=1 scope1_0_kind=Board scope1_0_value=Board scope2count=1 scope2_0_kind=Board scope2_0_value=Board commentlength=72 // Protel DXP Scope 1 Expression Was: InDifferentialPairClass('90_OHM')
DiffPairsRouting [All] p0: scope1count=1 scope1_0_kind=Board scope1_0_value=Board scope2count=1 scope2_0_kind=Board scope2_0_value=Board commentlength=0
DiffPairsRouting Diff_100ohm [InDifferentialPairClass('100_OHM')] p1: maxlimit=5 minlimit=5 mostfreqgap=5 toplayer_minwidth=4 toplayer_maxwidth=5.2 toplayer_prefwidth=5.2 midlayer1_minwidth=4 midlayer1_maxwidth=5.2 midlayer1_prefwidth=5.2 midlayer2_minwidth=4 midlayer2_maxwidth=5.2 midlayer2_prefwidth=5.2 midlayer3_minwidth=4 midlayer3_maxwidth=5.2 midlayer3_prefwidth=5.2 midlayer4_minwidth=4 midlayer4_maxwidth=5.2 midlayer4_prefwidth=5.2 bottomlayer_minwidth=4 bottomlayer_maxwidth=5.2 bottomlayer_prefwidth=5.2 maxuncoupledlength=500
DiffPairsRouting Diff_90ohm [InDifferentialPairClass('90_OHM')] p2: maxlimit=5 minlimit=5 mostfreqgap=5 toplayer_minwidth=5.2 toplayer_maxwidth=5.2 toplayer_prefwidth=5.2 midlayer1_minwidth=6 midlayer1_maxwidth=6 midlayer1_prefwidth=6 midlayer2_minwidth=6 midlayer2_maxwidth=6 midlayer2_prefwidth=6 midlayer3_minwidth=6 midlayer3_maxwidth=6 midlayer3_prefwidth=6 midlayer4_minwidth=6 midlayer4_maxwidth=6 midlayer4_prefwidth=6 bottomlayer_minwidth=6 bottomlayer_maxwidth=6 bottomlayer_prefwidth=6 maxuncoupledlength=500
DiffPairsRouting [All] p3: maxlimit=5 minlimit=4 mostfreqgap=5 toplayer_minwidth=4 toplayer_maxwidth=6 toplayer_prefwidth=5.2 midlayer1_minwidth=4 midlayer1_maxwidth=6 midlayer1_prefwidth=5.2 midlayer2_minwidth=4 midlayer2_maxwidth=6 midlayer2_prefwidth=5.2 midlayer3_minwidth=4 midlayer3_maxwidth=6 midlayer3_prefwidth=5.2 midlayer4_minwidth=4 midlayer4_maxwidth=6 midlayer4_prefwidth=5.2 bottomlayer_minwidth=4 bottomlayer_maxwidth=6 bottomlayer_prefwidth=5.2 maxuncoupledlength=500
FabricationTestPointUsage [All] p0: scope1count=1 scope1_0_kind=Board scope1_0_value=Board scope2count=1 scope2_0_kind=Board scope2_0_value=Board commentlength=0 valid=0 allowmultiple=FALSE
FabricationTestpoint [All] p0: scope1count=1 scope1_0_kind=Board scope1_0_value=Board scope2count=1 scope2_0_kind=Board scope2_0_value=Board commentlength=0 side=3 testpointundercomponent=TRUE minsize=40 maxsize=100 preferedsize=60 minholesize=0 maxholesize=40 preferedholesize=32 testpointgrid=1
FanoutControl Fanout_BGA [All] p0 off: scope1count=1 scope1_0_kind=Board scope1_0_value=Board scope2count=1 scope2_0_kind=Board scope2_0_value=Board commentlength=69 // Protel DXP Scope 1 Expression Was: IsBGA   Fanout_BGA (Default Rule)
FanoutControl Fanout_LCC [All] p0 off: scope1count=1 scope1_0_kind=Board scope1_0_value=Board scope2count=1 scope2_0_kind=Board scope2_0_value=Board commentlength=69 // Protel DXP Scope 1 Expression Was: IsLCC   Fanout_LCC (Default Rule)
FanoutControl Fanout_SOIC [All] p0 off: scope1count=1 scope1_0_kind=Board scope1_0_value=Board scope2count=1 scope2_0_kind=Board scope2_0_value=Board commentlength=71 // Protel DXP Scope 1 Expression Was: IsSOIC   Fanout_SOIC (Default Rule)
FanoutControl Fanout_Small [All] p0 off: scope1count=1 scope1_0_kind=Board scope1_0_value=Board scope2count=1 scope2_0_kind=Board scope2_0_value=Board commentlength=84 // Protel DXP Scope 1 Expression Was: (CompPinCount < 5)   Fanout_Small (Default Rule)
FanoutControl Fanout_Default [All] p0: scope1count=1 scope1_0_kind=Board scope1_0_value=Board scope2count=1 scope2_0_kind=Board scope2_0_value=Board commentlength=30 // Fanout_Default (Default Rule)
Height [All] p0: scope1count=1 scope1_0_kind=Board scope1_0_value=Board scope2count=1 scope2_0_kind=Board scope2_0_value=Board commentlength=0
HoleSize [All] p0: scope1count=1 scope1_0_kind=Board scope1_0_value=Board scope2count=1 scope2_0_kind=Board scope2_0_value=Board commentlength=0 absolutevalues=TRUE maxlimit=200 minlimit=5.9 maxpercent=80.000 minpercent=20.000
HoleSize [All] p1: absolutevalues=TRUE maxlimit=200 minlimit=5.9 maxpercent=80.000 minpercent=20.000
HoleToHoleClearance [All] p0: scope1count=1 scope1_0_kind=Board scope1_0_value=Board scope2count=1 scope2_0_kind=Board scope2_0_value=Board commentlength=0
LayerPairs [All] p0: scope1count=1 scope1_0_kind=Board scope1_0_value=Board scope2count=1 scope2_0_kind=Board scope2_0_value=Board commentlength=0 enforce=TRUE
Length DIFF_2 [All] p0 off: scope1count=1 scope1_0_kind=Board scope1_0_value=Board scope2count=1 scope2_0_kind=Board scope2_0_value=Board commentlength=72 maxlimit=2250 minlimit=2200 // Protel DXP Scope 1 Expression Was: InDifferentialPairClass('90_OHM')
Length DIFF_1 [All] p0 off: scope1count=1 scope1_0_kind=Board scope1_0_value=Board scope2count=1 scope2_0_kind=Board scope2_0_value=Board commentlength=73 maxlimit=1910 minlimit=1880 // Protel DXP Scope 1 Expression Was: InDifferentialPairClass('100_OHM')
Length QSPI [All] p0 off: scope1count=1 scope1_0_kind=Board scope1_0_value=Board scope2count=1 scope2_0_kind=Board scope2_0_value=Board commentlength=61 maxlimit=1160 minlimit=950 // Protel DXP Scope 1 Expression Was: InxSignalClass('QSPI')
Length Length_2 [All] p0: scope1count=1 scope1_0_kind=Board scope1_0_value=Board scope2count=1 scope2_0_kind=Board scope2_0_value=Board commentlength=0 maxlimit=20000 minlimit=0
Length DIFF_2 [InDifferentialPairClass('90_OHM')] p1: maxlimit=2250 minlimit=2200
Length DIFF_1 [InDifferentialPairClass('100_OHM')] p2: maxlimit=1910 minlimit=1880
Length QSPI [InxSignalClass('QSPI')] p3: maxlimit=1160 minlimit=950
Length Length_2 [All] p4: maxlimit=20000 minlimit=0
MatchedLengths SPI_2_NEW [All] p0 off: scope1count=1 scope1_0_kind=Board scope1_0_value=Board scope2count=1 scope2_0_kind=Board scope2_0_value=Board commentlength=61 tolerance=500 amplitude=200 gap=20 style=90-Degree // Protel DXP Scope 1 Expression Was: InxSignalClass('SPI2')
MatchedLengths LVDS_1 [All] p0 off: scope1count=1 scope1_0_kind=Board scope1_0_value=Board scope2count=1 scope2_0_kind=Board scope2_0_value=Board commentlength=61 tolerance=5 amplitude=200 gap=20 style=90-Degree // Protel DXP Scope 1 Expression Was: InxSignalClass('LVDS')
MatchedLengths DATA-0-7 [All] p0 off: scope1count=1 scope1_0_kind=Board scope1_0_value=Board scope2count=1 scope2_0_kind=Board scope2_0_value=Board commentlength=65 tolerance=200 amplitude=200 gap=20 style=90-Degree // Protel DXP Scope 1 Expression Was: InxSignalClass('DATA_0_7')
MatchedLengths MUX_TO_J1 [All] p0 off: scope1count=1 scope1_0_kind=Board scope1_0_value=Board scope2count=1 scope2_0_kind=Board scope2_0_value=Board commentlength=66 tolerance=250 amplitude=200 gap=20 style=90-Degree // Protel DXP Scope 1 Expression Was: InxSignalClass('mux_to_j1')
MatchedLengths MUX_J5 [All] p0 off: scope1count=1 scope1_0_kind=Board scope1_0_value=Board scope2count=1 scope2_0_kind=Board scope2_0_value=Board commentlength=66 tolerance=250 amplitude=200 gap=20 style=90-Degree // Protel DXP Scope 1 Expression Was: InxSignalClass('mux_to_j5')
MatchedLengths U2_MUX [All] p0 off: scope1count=1 scope1_0_kind=Board scope1_0_value=Board scope2count=1 scope2_0_kind=Board scope2_0_value=Board commentlength=66 tolerance=250 amplitude=200 gap=20 style=90-Degree // Protel DXP Scope 1 Expression Was: InxSignalClass('U2_TO_MUX')
MatchedLengths SPI_2_NEW [InxSignalClass('SPI2')] p1: tolerance=500 checknetsindiffpair=FALSE checkdiffpairvsdiffpair=TRUE checkxsignals=TRUE checkothers=TRUE
MatchedLengths LVDS_1 [InxSignalClass('LVDS')] p2: tolerance=5 checknetsindiffpair=FALSE checkdiffpairvsdiffpair=TRUE checkxsignals=TRUE checkothers=TRUE
MatchedLengths DATA-0-7 [InxSignalClass('DATA_0_7')] p3: tolerance=200 checknetsindiffpair=FALSE checkdiffpairvsdiffpair=TRUE checkxsignals=TRUE checkothers=TRUE
MatchedLengths MUX_TO_J1 [InxSignalClass('mux_to_j1')] p4: tolerance=250 checknetsindiffpair=FALSE checkdiffpairvsdiffpair=TRUE checkxsignals=TRUE checkothers=TRUE
MatchedLengths MUX_J5 [InxSignalClass('mux_to_j5')] p5: tolerance=250 checknetsindiffpair=FALSE checkdiffpairvsdiffpair=TRUE checkxsignals=TRUE checkothers=TRUE
MatchedLengths U2_MUX [InxSignalClass('U2_TO_MUX')] p6: tolerance=250 checknetsindiffpair=FALSE checkdiffpairvsdiffpair=TRUE checkxsignals=TRUE checkothers=TRUE
MinimumAnnularRing [All] p0: scope1count=1 scope1_0_kind=Board scope1_0_value=Board scope2count=1 scope2_0_kind=Board scope2_0_value=Board commentlength=0 minimumring=3.9
MinimumAnnularRing [All] p1: minimumring=3.9
MinimumSolderMaskSliver [All] p0: scope1count=1 scope1_0_kind=Board scope1_0_value=Board scope2count=1 scope2_0_kind=Board scope2_0_value=Board commentlength=0
MinimumSolderMaskSliver [All] p1: minsoldermaskwidth=4
NetAntennae [All] p0: scope1count=1 scope1_0_kind=Board scope1_0_value=Board scope2count=1 scope2_0_kind=Board scope2_0_value=Board commentlength=0
PasteMaskExpansion [All] p0: scope1count=1 scope1_0_kind=Board scope1_0_value=Board scope2count=1 scope2_0_kind=Board scope2_0_value=Board commentlength=0 expansion=0
PlaneClearance [All] p0: scope1count=1 scope1_0_kind=Board scope1_0_value=Board scope2count=1 scope2_0_kind=Board scope2_0_value=Board commentlength=0 clearance=20
PlaneConnect [All] p0: scope1count=1 scope1_0_kind=Board scope1_0_value=Board scope2count=1 scope2_0_kind=Board scope2_0_value=Board commentlength=0 planeconnectstyle=Direct reliefexpansion=20 reliefentries=4 reliefconductorwidth=10 reliefairgap=10
PlaneConnect [All] p1: planeconnectstyle=Direct reliefexpansion=20 reliefentries=4 reliefconductorwidth=10 reliefairgap=10
PolygonConnect [All] p0: scope1count=1 scope1_0_kind=Board scope1_0_value=Board scope2count=1 scope2_0_kind=Board scope2_0_value=Board commentlength=0 connectstyle=Direct reliefconductorwidth=10 reliefentries=4 polygonreliefangle="90 Angle"
PolygonConnect [All] p1: connectstyle=Direct reliefconductorwidth=10 reliefentries=4 polygonreliefangle="90 Angle" airgapwidth=10
RoomDefinition DUT [All] p0: scope1count=1 scope1_0_kind=ComponentClass scope1_0_value=DUT scope2count=1 scope2_0_kind=Board scope2_0_value=Board commentlength=0 region_x1=30930000 region_y1=24735000 region_x2=41000000 region_y2=36225000 confinementstyle=ConfineIn
RoomDefinition COUPLE [All] p0 off: scope1count=1 scope1_0_kind=Board scope1_0_value=Board scope2count=1 scope2_0_kind=Board scope2_0_value=Board commentlength=63 region_x1=25869300 region_y1=40166500 region_x2=33615700 region_y2=42076600 confinementstyle=ConfineOut // Protel DXP Scope 1 Expression Was: WithinRoom('CO_PLANNER')
RoomDefinition DUT [InComponentClass('DUT')] p1: confinementstyle=ConfineIn formatcopy=TRUE lockcomponents=FALSE outline 2143,1735.5 2154,1746.5 3074,1746.5 3100,1720.5 3100,619.5 3078,597.5 2381,597.5 2306,672.5 2306,1214.5 2269,1251.5 2156,1251.5 2093,1314.5 2093,1712.5 2116,1735.5
RoomDefinition COUPLE [WithinRoom('CO_PLANNER')] p2: confinementstyle=ConfineOut formatcopy=TRUE lockcomponents=FALSE outline 1592.53,2331.66 1593.27,2330.92 2361.57,2330.92 2361.57,2143.54 2358.68,2140.65 1974.97,2140.65 1965.68,2149.94 1965.68,2214.31 1595.03,2214.31 1586.93,2222.41
RoutingCorners [All] p0: scope1count=1 scope1_0_kind=Board scope1_0_value=Board scope2count=1 scope2_0_kind=Board scope2_0_value=Board commentlength=0 cornerstyle=45-Degree minsetback=100 maxsetback=100
RoutingLayers [All] p0: scope1count=1 scope1_0_kind=Board scope1_0_value=Board scope2count=1 scope2_0_kind=Board scope2_0_value=Board commentlength=0 top layer=Automatic mid layer 1=Automatic mid layer 2=Automatic mid layer 3=Automatic mid layer 4=Automatic bottom layer=Automatic
RoutingPriority [All] p0: scope1count=1 scope1_0_kind=Board scope1_0_value=Board scope2count=1 scope2_0_kind=Board scope2_0_value=Board commentlength=0
RoutingTopology [All] p0: scope1count=1 scope1_0_kind=Board scope1_0_value=Board scope2count=1 scope2_0_kind=Board scope2_0_value=Board commentlength=0 topology=Shortest
RoutingVias [All] p0: scope1count=1 scope1_0_kind=Board scope1_0_value=Board scope2count=1 scope2_0_kind=Board scope2_0_value=Board commentlength=0 holewidth=12.2 width=22.4 viastyle="Through Hole" minholewidth=5.9 minwidth=13 maxholewidth=24 maxwidth=50
RoutingVias [All] p1: holewidth=12.2 width=22.4 viastyle="Through Hole" minholewidth=5.9 minwidth=13 maxholewidth=24 maxwidth=50
ShortCircuit [All] p0: scope1count=1 scope1_0_kind=Board scope1_0_value=Board scope2count=1 scope2_0_kind=Board scope2_0_value=Board commentlength=0 allowed=FALSE
SilkToBoardRegionClearance [All] p0 off: scope1count=1 scope1_0_kind=Board scope1_0_value=Board scope2count=1 scope2_0_kind=Board scope2_0_value=Board commentlength=130 // Protel DXP Scope 1 Expression Was: Not ((IsComment or IsDesignator) And (Hide <> 'False')) and not InRegion(1000,500,4000,800)
SilkToBoardRegionClearance [Not ((IsComment or IsDesignator) And (Hide <> 'False')) and not InRegion(1000,500,4000,800)] p1:
SilkToSilkClearance [All] p0: scope1count=1 scope1_0_kind=Board scope1_0_value=Board scope2count=1 scope2_0_kind=Board scope2_0_value=Board commentlength=0
SilkToSilkClearance [All] p1: silktosilkclearance=3
SilkToSolderMaskClearance SilkscreenOverComponentPads [All] p0 off: scope1count=1 scope1_0_kind=Board scope1_0_value=Board scope2count=1 scope2_0_kind=Board scope2_0_value=Board commentlength=44 // Protel DXP Scope 1 Expression Was: IsPad
SilkToSolderMaskClearance SilkscreenOverComponentPads [IsPad] p1: minsilkscreentomaskgap=3 clearancetoexposedcopper=TRUE
SolderMaskExpansion [All] p0: scope1count=1 scope1_0_kind=Board scope1_0_value=Board scope2count=1 scope2_0_kind=Board scope2_0_value=Board commentlength=0 expansion=0
SolderMaskExpansion [All] p1: expansion=0
UnRoutedNet [All] p0: scope1count=1 scope1_0_kind=Board scope1_0_value=Board scope2count=1 scope2_0_kind=Board scope2_0_value=Board commentlength=0
UnpouredPolygon [All] p0: scope1count=1 scope1_0_kind=Board scope1_0_value=Board scope2count=1 scope2_0_kind=Board scope2_0_value=Board commentlength=0
ViasUnderSMD [All] p0: scope1count=1 scope1_0_kind=Board scope1_0_value=Board scope2count=1 scope2_0_kind=Board scope2_0_value=Board commentlength=0 allowed=FALSE
ViasUnderSMD [All] p1: allowed=FALSE
Width Width_1 [All] p0: scope1count=1 scope1_0_kind=Board scope1_0_value=Board scope2count=1 scope2_0_kind=Board scope2_0_value=Board commentlength=0 maxlimit=100 minlimit=4 preferedwidth=10
Width Width_pmic [All] p0 off: scope1count=1 scope1_0_kind=Board scope1_0_value=Board scope2count=1 scope2_0_kind=Board scope2_0_value=Board commentlength=57 maxlimit=100 minlimit=4 preferedwidth=5 // Protel DXP Scope 1 Expression Was: WithinRoom('PMIC')
Width Width_100 [All] p0 off: scope1count=1 scope1_0_kind=Board scope1_0_value=Board scope2count=1 scope2_0_kind=Board scope2_0_value=Board commentlength=70 maxlimit=5.2 minlimit=5 preferedwidth=5 // Protel DXP Scope 1 Expression Was: InDifferentialPairClass('DIIF')
Width Width_50ohm [All] p0: scope1count=1 scope1_0_kind=NetClass scope1_0_value=50_OHM scope2count=1 scope2_0_kind=Board scope2_0_value=Board commentlength=0 maxlimit=11 minlimit=9 preferedwidth=9
Width Width_PWR [All] p0: scope1count=1 scope1_0_kind=NetClass scope1_0_value=PWR scope2count=1 scope2_0_kind=Board scope2_0_value=Board commentlength=0 maxlimit=100 minlimit=6 preferedwidth=25
Width Width_room1 [All] p0: scope1count=1 scope1_0_kind=Board scope1_0_value=Board scope2count=1 scope2_0_kind=Board scope2_0_value=Board commentlength=0 maxlimit=100 minlimit=10 preferedwidth=20
Width Width_1 [All] p1: maxlimit=100 minlimit=4 preferedwidth=10 minimp=50.000000 maximp=50.000000 favimp=50.000000
Width Width_pmic [WithinRoom('PMIC')] p2: maxlimit=100 minlimit=4 preferedwidth=5 toplayer_prefwidth=4 midlayer1_minwidth=5 midlayer2_minwidth=5 midlayer3_minwidth=5 midlayer4_minwidth=5 bottomlayer_prefwidth=4 minimp=50.000000 maximp=50.000000 favimp=50.000000
Width Width_100 [InDifferentialPairClass('DIIF')] p3: maxlimit=5.2 minlimit=5 preferedwidth=5 toplayer_minwidth=5.2 toplayer_prefwidth=5.2 midlayer1_maxwidth=5 midlayer2_maxwidth=5 midlayer3_maxwidth=5 midlayer4_maxwidth=5 bottomlayer_maxwidth=5 minimp=50.000000 maximp=50.000000 favimp=50.000000
Width Width_50ohm [InNetClass('50_OHM')] p4: maxlimit=11 minlimit=9 preferedwidth=9 toplayer_minwidth=11 toplayer_prefwidth=11 midlayer1_minwidth=0 midlayer1_maxwidth=0 midlayer1_prefwidth=0 midlayer2_maxwidth=9 midlayer3_maxwidth=9 midlayer4_minwidth=0 midlayer4_maxwidth=0 midlayer4_prefwidth=0 bottomlayer_maxwidth=9 minimp=50.000000 maximp=50.000000 favimp=50.000000
Width Width_PWR [InNetClass('PWR')] p5: maxlimit=100 minlimit=6 preferedwidth=25
Width Width_room1 [All] p6: maxlimit=100 minlimit=10 preferedwidth=20
23 further rules are at their usual default settings.

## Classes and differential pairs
net class USB: XDSET_1_D_N XDSET_1_D_P
net class Undefined: AR_LVDS_0_N AR_LVDS_0_P AR_LVDS_1_N AR_LVDS_1_P AR_LVDS_CLK_N AR_LVDS_CLK_P AR_LVDS_FRCLK_N AR_LVDS_FRCLK_P NetJ1_26 NetJ1_28 NetJ1_44 NetJ1_46 NetJ1_50 NetJ1_52 NetJ1_56 NetJ1_58 VCC_LDO_OUT
net class QSPI: AR_QSPI_CS AR_QSPI_D0 AR_QSPI_D1 AR_QSPI_D2 AR_QSPI_D3 AR_QSPI_SCLK NetR39_2 NetR40_1 NetR42_2 NetR44_1 NetR45_1
net class PWR: 1V8 1V24 3V3 5VBST +3.3VD AR_1P0_RF1 AR_1P0_RF2 AR_1V4_APLL AR_1V4_SYNTH AR_1V8 AR_1V24 AR_3V3 AR_VBGAP AR_VOUT_PA GND MCU_3V3 MCU_5V NetC1_2 NetC16_2 NetC79_1 NetC85_1 NetJ1_1 NetR3_1 NetR86_1 NetR197_1 VBUS_1_DETECT VDDC_1 VIN VPP_1P7
component class "PROC051C_XDS110 Interface_1B": C49 C63 C66 C67 C70 C71 R123 R124 R125 R126 R127 R128 R129 R134 R135 R136 R140 R152 R154 R155 U6 U7 Y2
component class "PROC051C_XDS110 Interface_1A": C41 C42 C43 C50 C61 C62 C64 C69 C74 C75 C76 J8 R151 R153 R161 R174 R175 U10
component class PROC051C_VPP_Supply: C85 C86 C88 P7 R61 R193 R194 U11
component class PROC051C_Tempsensor: C91 C92 R3 R5 R167 R168 R196 R197 R198 R199 R200 R201 U12 U13
component class PROC051C_SOP_Headers_Reference: R88 R89 R92 R93 R95 R96 R97 R98 R99 R101 R112 R113 R114 S1
component class PROC051C_RST_LEDs: C11 D2 DS1 DS2 DS3 DS4 Q1 Q2 R68 R72 R73 R74 R77 R79 R80 R90 R103 R110 R116 R117 R130 R133 R160 R202 SW1 SW2
component class PROC051C_QSPI_Flash_Reference: C1 C2 R37 R38 R39 R40 R41 R42 R43 R44 R45 U1
component class PROC051C_PWR_In_Reference: C18 C21 C22 C23 C25 C26 C27 C28 C29 C30 C31 C32 C33 C34 C35 C36 C38 C40 C44 C46 C54 C59 C60 C68 C72 C73 C77 C78 C79 C81 C82 C93 C94 C95 C96 D5 F1 L1 L2 L3 L4 L7 P6 R82 R83 R84 R118 R119 R120 R121 R122 R131 R132 R138 R139 R141 R142 R143 R144 R145 R146 R147 R148 R149 R150 R156 R157 R158 R159 R186 R188 R189 R190 TP1 TP2 TP3 U4 U5 U8
component class "PROC051C_LP Connector": J5 J6 P1 R1 R2 R4 R6 R8 R9 R10 R18 R19 R24 R25 R26 R31 R32 R35 R36 R60 R76 R94 R102 R104 R105 R106 R107 R108 R109 R115 R162 R163 R164 R165 R166 R169 R172 R173
component class PROC051C_LC_Filtering_Reference: C19 C37 C55 C80 C98 C99 C100 C102 C103 C104 C105 L5 L6 L8 L9 L10 R137
component class "PROC051C_HD Connector": J1 J2 R7 R17 R20 R21 R22 R23 R27 R28 R29 R30 R33 R34 R48 R49 R50 R51 R52 R53 R54 R55 R56 R57 R58 R59 R62 R63 R64 R65 R66 R67 R69 R70 R71 R75 R111 R179 R180 R181 R182 R183 R184
component class PROC051C_DUT_Reference: C8 C9 C15 R13 R14 R15 R16 R46 R47 R81 R91 R100 R170 R171 U2 Y1
component class PROC051C_Decoupling_Caps_Reference: C3 C4 C5 C6 C7 C10 C12 C13 C14 C17 C39 C45 C47 C48 C51 C52 C53 C56 C57 C58 C65 C83 C84 C87 C89 C90 C101
component class PROC051C_CAN_Interface: C16 C20 C24 C97 J3 R11 R12 R78 R85 R86 R87 R177 R178 R208 S2 U3 U14
component class Header: P1 P7
component class Label: LBL1
component class AssemblyNote: ZZ1 ZZ2 ZZ3 ZZ4 ZZ5
component class FiducialMark: FID1 FID2 FID3 FID4 FID5 FID6
component class PROC051C_Hardware: "CAUTION HOT SURFACE" "ESD Susceptible" FID1 FID2 FID3 FID4 FID5 FID6 LBL1 Logo1 Logo2 LOGO3 Logo4 ZZ1 ZZ2 ZZ3 ZZ4 ZZ5
component class Logo: Logo1
net class RX_TX: RX1 RX2 RX3 RX4 TX1 TX2 TX3
component class Shunt: Z20 Z21
differential pair AR_LVDS_FRCLK: +AR_LVDS_FRCLK_P -AR_LVDS_FRCLK_N
differential pair AR_LVDS_CLK: +AR_LVDS_CLK_P -AR_LVDS_CLK_N
differential pair AR_LVDS_1: +AR_LVDS_1_P -AR_LVDS_1_N
differential pair AR_LVDS_0: +AR_LVDS_0_P -AR_LVDS_0_N
differential pair " ": +XDSET_1_D_P -XDSET_1_D_N

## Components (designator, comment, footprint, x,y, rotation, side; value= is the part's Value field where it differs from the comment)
C1 "GCM188R71C105KA64D" 0603 2106,2038 r270 top
C2 "CGA2B3X7R1H104K050BB" 0402L 2044.9,2028.9 r270 top
C3 "GCM155R71C224KE02D" 0402L 2352,1745 r270 top
C4 "GCM155R71C104KA55D" 0402L 2010,1484 r0 top
C5 "GCM155R71C224KE02D" 0402L 2211.95,1767.6 r270 top
C6 "GCM155R71C104KA55D" 0402L 2034.5,1705.6 r270 top
C7 "GCM155R71C224KE02D" 0402L 2218.07,1606.5 r180 bottom
C8 "GRM033C71A104KE14D" 0201 2137,1566 r90 bottom
C9 "GJM1555C1H4R7BB01D" 0402L 1842.36,1324.73 r90 top
C10 "GCM155R71C224KE02D" 0402L 2468,1233 r180 top
C11 "GCM155R71C104KA55D" 0402L 197.3,1284.9 r270 top
C12 "GCM155R71C224KE02D" 0402L 2167.2,1209.2 r90 top
C13 "GCM188R71C105KA64D" 0603 2226.5,1187.9 r90 top
C14 "GCM188R71C105KA64D" 0603 2084.45,1189.4 r90 top
C15 "GJM1555C1H4R7BB01D" 0402L 1954,1180.4 r0 top
C16 "C0402C104K8RACTU" 0402L 969.6,920 r0 top
C17 "GCM21BR71A106KE22L" 0805_HV 2188,1040 r180 top
C18 "Capacitor" 0402S 2508,319 r0 bottom
C19 "CGA5L1X7R0J226M160AC" 1206_180 1712.34,1703.29 r0 bottom
C20 "C0402C104K8RACTU" 0402L 967.19,798.85 r0 top
C21 "CGA6P1X7R1E106M250AC" 1210_280 2249,158 r180 bottom
C22 "GCM155R71C104KA55D" 0402 2177,503 r0 bottom
C23 "06035C473JAT2A" 0603 2382,230 r90 bottom
C24 "GCM155R71H472KA37D" 0402 1117.1,691.1 r90 top
C25 "CGA6P1X7R1E106M250AC" 1210_280 2731,24 r0 bottom
C26 "T491B476K010AT" 3528-21 2689,-59 r0 top
C27 "06035C473JAT2A" 0603 2713,116 r0 bottom
C28 "Capacitor" 0402S 2514.45,28.45 r0 bottom
C29 "GCM32ER71C226KE19L" 1210_280 2996,218 r0 bottom
C30 "GCM32ER71C226KE19L" 1210_280 2996,340 r0 bottom
C31 "GCM32ER71C226KE19L" 1210_280 2940,462 r0 bottom
C32 "CGA4J1X7R1E475K125AC" 0805L 2445,-5 r270 bottom
C33 "GCM188R71C105KA64D" 0603 1446,978 r0 bottom
C34 "Capacitor" 0402 1445,1029 r180 bottom
C35 "Capacitor" 0805_HV1 1907,655 r270 bottom
C36 "GCM188R71C105KA64D" 0603 1977,658 r90 bottom
C37 "CGA5L1X7R0J226M160AC" 1206_180 1417.79,1817.69 r90 bottom
C38 "GCM31CR70J226KE23L" 1206_180 2319,892 r180 bottom
C39 "GCM155R71C224KE02D" 0402L 2440,1629 r180 bottom
C40 "GCM21BR71A106KE22L" 0805_HV 1518.99,876.94 r270 bottom
C41 "GCM155C71A105KE38D" 0402_070 558.3,1631.85 r90 bottom
C42 "C0402C104K8RACTU" 0402L 518.22,1631.85 r270 bottom
C43 "C0402C104K8RACTU" 0402L 362.52,1629.85 r270 bottom
C44 "GCM32ER70J476KE19L" 1210_270 1532,1371.13 r0 bottom
C45 "GCM21BR71A106KE22L" 0805_HV 2481.19,1533.91 r270 bottom
C46 "Capacitor" 0805_HV1 2446.07,657 r270 bottom
C47 "GCM155R71C224KE02D" 0402L 2424.67,1506.62 r270 bottom
C48 "GCM155R71C224KE02D" 0402L 2329,1654 r90 bottom
C49 "C0402C104K8RACTU" 0402L 894.35,1481.9 r180 bottom
C50 "C0402C103K4RACTU" 0402L 145.95,1448.7 r270 bottom
C51 "GCM155R71C224KE02D" 0402L 2387.91,1370.16 r90 bottom
C52 "GCM21BR71A106KE22L" 0805_HV 2445.08,1380.29 r90 bottom
C53 "GCM155R71C224KE02D" 0402L 2072,1342 r0 bottom
C54 "GCM188R71C105KA64D" 0603 2376.63,659.76 r90 bottom
C55 "GCM21BR71A106KE22L" 0805_HV 1729.71,1223.91 r180 bottom
C56 "GCM155R71C224KE02D" 0402L 2284.84,1348 r180 bottom
C57 "GCM155R71C224KE02D" 0402L 2579,1296.68 r90 bottom
C58 "GCM21BR71A106KE22L" 0805_HV 2642,1282 r90 bottom
C59 "Capacitor" 0805_HV 1667,1088 r90 bottom
C60 "GCM31CR70J226KE23L" 1206_180 1983.24,893.57 r0 bottom
C61 "GCM155C71A105KE38D" 0402_070 127.65,1240.06 r180 bottom
C62 "GCM155C71A105KE38D" 0402_070 901,1201 r0 bottom
C63 "GCM1555C1H8R0DA16D" 0402L 1006,1150 r0 bottom
C64 "C0402C104K8RACTU" 0402L 903,1159 r180 bottom
C65 "GCM21BR71A106KE22L" 0805_HV 2416,1183.57 r0 bottom
C66 "C0402C103K4RACTU" 0402L 127.19,1130.1 r0 bottom
C67 "C0402C104K8RACTU" 0402L 127.25,1088.8 r0 bottom
C68 "GCM31CR70J226KE23L" 1206_180 1980.84,981 r0 bottom
C69 "C0402C103K4RACTU" 0402L 127.65,1003.56 r0 bottom
C70 "GCM1555C1H8R0DA16D" 0402L 1039,983 r0 bottom
C71 "C0402C104K8RACTU" 0402L 814,1010.5 r180 top
C72 "GCM155R71E103KA37D" 0402S 1519,1232 r0 bottom
C73 "GCM155R71E103KA37D" 0402S 1562,1004 r0 bottom
C74 "C1005X7S1A225K050BC" 0402_065L 516.6,857.15 r90 bottom
C75 "C0402C104K8RACTU" 0402L 473.68,857.15 r90 bottom
C76 "GCM155C71A105KE38D" 0402_070 364,871 r270 bottom
C77 "Capacitor" 0402 2382,562 r0 bottom
C78 "Capacitor" 0402 2765,460 r0 bottom
C79 "CGA4J1X7R1E475K125AC" 0805L 2185,11 r270 top
C80 "GCM21BR71A106KE22L" 0805_HV 2640.38,807 r270 bottom
C81 "Capacitor" 0805_HV1 1837,420.37 r270 bottom
C82 "0402YC104KAT2A" 0402 2053,502 r180 bottom
C83 "GCM21BR71A106KE22L" 0805_HV 2477,1114 r90 top
C84 "GCM155R71C224KE02D" 0402L 1914,1419 r0 top
C85 "GRM155R70J105MA12D" 0402 397.9,940.5 r0 top
C86 "C1005X7S1A225K050BC" 0402_065L 409.8,1129.1 r180 top
C87 "GCM188R70J225KE22D" 0603 2261.8,1791.4 r270 top
C88 "C0402C330J5GAC" 0402L 526,900.4 r0 top
C89 "GCM188R70J225KE22D" 0603 1982.1,1728.9 r270 top
C90 "GCM155R71C224KE02D" 0402L 2182,1128 r90 top
C91 "C0402C104K8RACTU" 0402L 2041,858 r90 top
C92 "C0402C104K8RACTU" 0402L 263.6,916.2 r90 top
C93 "GRT21BR61E226ME13L" 0805_HV 1969,390 r180 bottom
C94 "GCM188R71C105KA64D" 0603 2327,400 r90 bottom
C95 "GCM21BR71A106KE22L" 0805_HV 1527.13,1485 r0 bottom
C96 "GCM21BR71A106KE22L" 0805_HV 1360.21,1328.48 r180 bottom
C97 "C0402C104K8RACTU" 0402L 1215,1245 r180 top
C98 "GCM21BR71A106KE22L" 0805_HV 1569,1654.51 r270 bottom
C99 "CGA5L1X7R0J226M160AC" 1206_180 2037.16,1208.67 r180 bottom
C100 "GCM21BR71A106KE22L" 0805_HV 2293,1838 r270 bottom
C101 "GCM155R71E103KA37D" 0402L 2010,1448 r180 top
C102 "GCM21BR71A106KE22L" 0805_HV 2654.2,1941.82 r90 bottom
C103 "GCM21BR71A106KE22L" 0805_HV 1335.31,1654.61 r270 bottom
C104 "GCM21BR71A106KE22L" 0805_HV 2097.09,1095.42 r270 bottom
C105 "CGA5L1X7R0J226M160AC" 1206_180 1754.95,1312 r180 bottom
"CAUTION HOT SURFACE" "CAUTION HOT SURFACE" IEC_HotSurface_Small 1560,1751 r0 top
D2 "SMS3923-040LF" SOD-882 53.73,1105.47 r0 top
D5 "APHHS1005CGCK" APHHS1005_Green 105,676 r90 top
DS1 "LS L29K-G1J2-1-Z" "LS L29K_Red" 157,676 r90 top
DS2 "LS L29K-G1J2-1-Z" "LS L29K_Red" 52,676 r270 top
DS3 "SML-E12Y8WT86" SML-E1_Yellow -18,676 r270 top
DS4 "SML-E12Y8WT86" SML-E1_Yellow 255.6,468.46 r270 top
"ESD Susceptible" "ESD Susceptible" ESD_Overlay_Small 960,1123 r0 top
F1 "0440005.WR" 1206 2127,127 r180 top
FID1 "Fiducial" FIDUCIAL10-20 196,-40.5 r90 top
FID2 "Fiducial" FIDUCIAL10-20 196,2287.5 r90 top
FID3 "Fiducial" FIDUCIAL10-20 3007,1857 r90 top
FID4 "Fiducial" FIDUCIAL10-20 196,2287.5 r90 bottom
FID5 "Fiducial" FIDUCIAL10-20 196,-40.5 r90 bottom
FID6 "Fiducial" FIDUCIAL10-20 3007,1857 r90 bottom
J1 "QSH-030-01-L-D-A" SAMTEC_QSH-030-01-X-D-A 813.64,1886.26 r270 top locked
J2 "128-0711-201" JOHNSON_128-0711-201 2159,252 r0 top
J3 "OSTTE030161" ON-SHORE_OSTTE030161 670.6,-25.28 r180 bottom
J5 "SSM-110-S-DV" SAMTEC_SSM-110-X-DV 977.5,2109.5 r0 bottom locked
J6 "SSM-110-S-DV" SAMTEC_SSM-110-X-DV 977.5,409.5 r0 bottom
J8 "105017-0001" CONN_105017-0001 1945,-131.01 r180 bottom
L1 "XAL5030-222MEB" XAL5030 2790,279 r0 bottom
L2 "DFE252012PD-R47M" DFE252012P 2347,797 r0 bottom
L3 "DFE252012PD-R47M" DFE252012P 1971,798.35 r180 bottom
L4 "DFE252012PD-1R0M" DFE252012P 1937,496 r90 bottom
L5 "NLCV32T-R10M-EFRD" NLCV32 1809.37,1080.62 r90 bottom
L6 "NLCV32T-R10M-EFRD" NLCV32 2212.35,1090.07 r90 bottom
L7 "HI2220P601R-10" 2220_345 2376,19 r270 top
L8 "BLM18KG121TH1D" 0603 1492.32,1657.42 r90 bottom
L9 "BLM18KG121TH1D" 0603 1430.22,1657.42 r90 bottom
L10 "NLCV32T-R10M-EFRD" NLCV32 2538.67,767.5 r90 bottom
LBL1 "Label" Label_650x200 2821,382 r0 top
Logo1 "Texas Instruments" TI_STACKED_OVERLAY_SMALL 668,1043 r90 top
Logo2 "FCC disclaimer" FCC_disclaimer 2420,2373 r0 top
LOGO3 "CE Mark" CE_Mark_5mm 1840,2250 r180 bottom
Logo4 "WEEE logo" WEEE_Minimum 2156,2270 r180 bottom
P1 "TSW-103-07-T-S" Samtec_TSW-103-07-T-S 6.27,1746.15 r270 top
P6 "PJ-051AH" CUI_PJ-051AH 1245.91,-136.37 r270 bottom
P7 "TSW-102-07-G-S" TSW-102-07-G-S 171.94,1796.15 r270 top
Q1 "BSS123" SOT-23 120.58,536.75 r90 top
Q2 "BSS123" SOT-23 130,394 r0 bottom
R1 "CRCW02010000Z0ED" 0201_Silk 1100,2347 r270 bottom
R2 "CRCW02010000Z0ED" 0201_Silk 930.05,2242.72 r270 top
R3 "CRCW040210K0FKED" 0402L 1884.3,857.1 r180 top
R4 "CRCW02010000Z0ED" 0201_Silk 1022.55,2242.72 r270 top
R5 "CRCW02010000Z0ED" 0201_Silk 1921,937 r0 top
R6 "CRCW02010000Z0ED" 0201_Silk 1128.05,2242.72 r270 top
R7 "CRCW02010000Z0ED" 0201_Silk 1161.25,2242.72 r270 top
R8 "CRCW02010000Z0ED" 0201_Silk 1348,2318 r90 bottom
R9 "CRCW02010000Z0ED" 0201_Silk 829.75,2241.72 r270 top
R10 "CRCW02010000Z0ED" 0201_Silk 1239.25,2241.72 r270 top
R11 "ERJ-2GE0R00X" 0402L 1165,1080 r270 top
R12 "ERJ-2GE0R00X" 0402L 900,1237 r270 top
R13 "CRCW040210K0FKED" 0402L 1198.4,2234.05 r270 top
R14 "CRCW040210K0FKED" 0402L 1042.9,2342.6 r180 bottom
R15 "CRCW040210K0FKED" 0402L 1114,2137.85 r270 top
R16 "CRCW040210K0FKED" 0402L 649,1846 r180 bottom
R17 "CRCW02010000Z0ED" 0201_Silk 1082,2242.72 r90 top
R18 "CRCW02010000Z0ED" 0201_Silk 1028.21,2130.07 r270 top
R19 "CRCW02010000Z0ED" 0201_Silk 419.25,2129.72 r270 top
R20 "CRCW02010000Z0ED" 0201_Silk 452.11,2129.72 r270 top
R21 "CRCW02010000Z0ED" 0201_Silk 484.35,2129.72 r270 top
R22 "CRCW02010000Z0ED" 0201_Silk 550.11,2129.72 r270 top
R23 "CRCW02010000Z0ED" 0201_Silk 582.61,2129.72 r270 top
R24 "CRCW02010000Z0ED" 0201_Silk 641.1,1885.6 r180 bottom
R25 "CRCW02010000Z0ED" 0201_Silk 755.8,1883.8 r180 bottom
R26 "CRCW02010000Z0ED" 0201_Silk 866.7,2129.6 r270 top
R27 "CRCW02010000Z0ED" 0201_Silk 898.8,2129.5 r270 top
R28 "CRCW02010000Z0ED" 0201_Silk 931.5,2129.4 r270 top
R29 "CRCW02010000Z0ED" 0201_Silk 963.83,2129.72 r270 top
R30 "CRCW02010000Z0ED" 0201_Silk 995.75,2129.72 r270 top
R31 "CRCW02010000Z0ED" 0201_Silk 1176.75,2129.72 r270 top
R32 "CRCW02010000Z0ED" 0201_Silk 1276,2129 r270 top
R33 "CRCW02010000Z0ED" 0201_Silk 517.39,2129.28 r270 top
R34 "CRCW20100000Z0EF" 2010 1433,2072 r0 top
R35 "CRCW02010000Z0ED" 0201_Silk 1334,1971 r90 top
R36 "CRCW02010000Z0ED" 0201_Silk 1427.25,1976.72 r90 top
R37 "ERJ-2GE0R00X" 0402L 2160,2028 r270 top
R38 "CRCW040247K5FKED" 0402L 1687.8,2021.84 r180 top
R39 "CRCW020133R2FNED" 0201_Silk 1656.9,1944.5 r90 top
R40 "CRCW020133R2FNED" 0201_Silk 2050,1960 r0 top
R41 "CRCW040210K0FKED" 0402L 2118.55,1950.98 r0 top
R42 "CRCW020133R2FNED" 0201_Silk 1708.5,1942.8 r90 top
R43 "CRCW040210K0FKED" 0402L 1683.2,1892 r180 top
R44 "CRCW020133R2FNED" 0201_Silk 2049.68,1920.35 r0 top
R45 "CRCW020133R2FNED" 0201_Silk 2050.68,1873.85 r0 top
R46 "CRCW04020000Z0ED" 0402 2629.9,1729.72 r270 bottom
R47 "Resistor" 0402L 1911,1474 r180 top
R48 "CRCW02010000Z0ED" 0201_Silk 475.61,1611.72 r270 top
R49 "CRCW02010000Z0ED" 0201_Silk 508.25,1611.72 r270 top
R50 "CRCW02010000Z0ED" 0201_Silk 540.75,1611.72 r270 top
R51 "CRCW02010000Z0ED" 0201_Silk 573.25,1611.72 r270 top
R52 "CRCW02010000Z0ED" 0201_Silk 605.75,1611.72 r270 top
R53 "CRCW02010000Z0ED" 0201_Silk 638.25,1611.72 r270 top
R54 "CRCW020120R0FNED" 0201_033 984,1874 r90 bottom
R55 "CRCW020120R0FNED" 0201_033 951,1873.8 r90 bottom
R56 "CRCW020120R0FNED" 0201_033 918.5,1873.3 r90 bottom
R57 "CRCW020120R0FNED" 0201_033 885.6,1873.3 r90 bottom
R58 "CRCW02010000Z0ED" 0201_Silk 800.55,1611.72 r270 top
R59 "CRCW02010000Z0ED" 0201_Silk 833.05,1611.72 r270 top
R60 "CRCW02010000Z0ED" 0201_Silk 688,2235 r270 top
R61 "ERJ-2RKF1002X" 0402 525.8,941.1 r180 top
R62 "CRCW02010000Z0ED" 0201_Silk 929.85,1611.72 r270 top
R63 "CRCW02010000Z0ED" 0201_Silk 962.11,1611.72 r270 top
R64 "CRCW02010000Z0ED" 0201_Silk 1026.61,1611.72 r270 top
R65 "CRCW02010000Z0ED" 0201_Silk 1059.25,1611.72 r270 top
R66 "CRCW02010000Z0ED" 0201_Silk 1091.75,1611.72 r270 top
R67 "CRCW02010000Z0ED" 0201_Silk 1124.25,1611.72 r270 top
R68 "ERJ-2GEJ101X" 0402L 246.04,1553.15 r90 top
R69 "CRCW02010000Z0ED" 0201_Silk 1059.25,1551.72 r270 top
R70 "CRCW02010000Z0ED" 0201_Silk 1091.75,1552.14 r270 top
R71 "CRCW02010000Z0ED" 0201_Silk 1124.33,1551.72 r270 top
R72 "CRCW02010000Z0ED" 0201_Silk 192.5,1461.25 r90 top
R73 "CRCW040210K0FKED" 0402L 192.05,1390.92 r90 top
R74 "CRCW040210K0FKED" 0402L 51.65,1221.14 r180 top
R75 "CRCW02010000Z0ED" 0201_Silk 1250,1176 r270 top
R76 "CRCW02010000Z0ED" 0201_Silk 1284,1176 r270 top
R77 "ERJ-2GEJ101X" 0402L 45,1258 r0 top
R78 "ERJ-2GE0R00X" 0402L 970,880 r180 top
R79 "ERJ-2GEJ101X" 0402L 242.25,1153.14 r180 top
R80 "ERJ-2GEJ101X" 0402L -27.26,1087.15 r90 top
R81 "Resistor" 0402L 2141,1309 r180 bottom
R82 "Resistor" 0402L 2570,13 r90 bottom
R83 "CRCW060320R0JNEA" 0603 1388.84,1205.26 r0 bottom
R84 "CRCW0402100KJNED" 0402 2392,77 r0 bottom
R85 "CRCW040261R9FKED" 0402L 1158,690.8 r90 top
R86 "CRCW040210K0FKED" 0402L 1246.3,794.7 r270 top
R87 "CRCW040261R9FKED" 0402L 1076.7,691.4 r270 top
R88 "CRCW040282K5FKED" 0402L 966.12,663.85 r270 top
R89 "CRCW040210K0FKED" 0402L 1006.58,663.55 r270 top
R90 "ERJ-2GEJ361X" 0402L 207,771 r90 top
R91 "CRCW040210K0FKED" 0402L 156,773 r90 bottom
R92 "CRCW04027K87FKED" 0402L 965.62,585.85 r270 top
R93 "CRCW0402750RFKED" 0402L 1005.82,585.85 r270 top
R94 "CRCW02010000Z0ED" 0201_Silk 828.25,532.28 r90 top
R95 "CRCW04027K87FKED" 0402L 648.82,524.55 r90 top
R96 "CRCW040282K5FKED" 0402L 608.78,524.25 r270 top
R97 "ERJ-2GE0R00X" 0402L 276.14,576.76 r90 top
R98 "CRCW040210K0FKED" 0402L 316,575 r90 top
R99 "CRCW04027K87FKED" 0402L 297,629 r180 top
R100 "CRCW04020000Z0ED" 0402 2649,1807.44 r0 bottom
R101 "CRCW0402750RFKED" 0402L 366.98,572.85 r90 top
R102 "CRCW02010000Z0ED" 0201_Silk 1230.25,500.28 r90 top
R103 "ERJ-2GEJ361X" 0402L -18,580 r270 top
R104 "CRCW02010000Z0ED" 0201_Silk 727.75,499.28 r90 top
R105 "CRCW02010000Z0ED" 0201_Silk 929.75,499.28 r90 top
R106 "CRCW02010000Z0ED" 0201_Silk 1030.25,499.28 r90 top
R107 "ERJ-2GE0R00X" 0402L 1129.75,499.28 r90 top
R108 "CRCW02010000Z0ED" 0201_Silk 1330.35,499.08 r90 top
R109 "CRCW02010000Z0ED" 0201_Silk 1367.85,499.08 r90 top
R110 "CRCW0402100KFKED" 0402L 7.72,523.77 r180 top
R111 "CRCW02010000Z0ED" 0201_Silk 2143,369 r0 top
R112 "CRCW0402750RFKED" 0402L 649.32,447.55 r270 top
R113 "CRCW040210K0FKED" 0402L 608.92,447.55 r90 top
R114 "CRCW040282K5FKED" 0402L 297,664 r0 top
R115 "CRCW20100000Z0EF" 2010 720,722 r0 bottom
R116 "ERJ-2GEJ511X" 0402L 7.78,480.33 r0 top
R117 "ERJ-2GEJ361X" 0402L 308.61,456.15 r90 top
R118 "CRCW0402220RJNED" 0402 88,783 r270 bottom
R119 "Resistor" 0402L 2272,347.69 r90 bottom
R120 "Resistor" 0402L 1584,1038 r180 bottom
R121 "Resistor" 0402L 2224,351 r90 bottom
R122 "ERA-2AEB1212X" 0402 1509,1273 r180 bottom
R123 "CRCW04021K00FKED" 0402L 757.28,1632.15 r90 bottom
R124 "CRCW04021K00FKED" 0402L 637.72,1631.85 r270 bottom
R125 "CRCW04024K87FKED" 0402L 677.52,1631.85 r270 bottom
R126 "CRCW04021K00FKED" 0402L 717.68,1632.15 r90 bottom
R127 "CRCW04021K00FKED" 0402L 598.12,1631.85 r270 bottom
R128 "ERJ-2GE0R00X" 0402L 246.5,1628.85 r270 bottom
R129 "ERJ-2GE0R00X" 0402L 287,1628.5 r270 bottom
R130 "MCT06030Z0000ZP500" 0603 2557,522 r0 bottom
R131 "Resistor" 0402S 2179,812 r90 bottom
R132 "Resistor" 0402S 2144,812 r90 bottom
R133 "MCT06030Z0000ZP500" 0603 2750,520 r180 bottom
R134 "CRCW040249R9FKED" 0402L 894.65,1440.6 r0 bottom
R135 "CRCW02010000Z0ED" 0201_Silk 134.78,1366.19 r0 bottom
R136 "CRCW02010000Z0ED" 0201_Silk 134.78,1334.29 r0 bottom
R137 "MCT06030Z0000ZP500" 0603 2498,1258 r180 bottom
R138 "CRCW0402100KFKED" 0402L 2545,396 r90 bottom
R139 "ERA-2AEB4871X" 0402 2664,414 r180 bottom
R140 "CRCW04021K00FKED" 0402L 127.65,1199.52 r0 bottom
R141 "ERJ-2GE0R00X" 0402L 2579,396 r90 bottom
R142 "CRCW040210K0JNED" 0402 2150,453 r0 bottom
R143 "Resistor" 0402L 2421,404 r90 bottom
R144 "Resistor" 0402L 1828,600 r270 bottom
R145 "ERA-2AEB4872X" 0402 1606,1280.92 r180 bottom
R146 "ERA-2ARB4421X" 0402 2560.62,460 r180 bottom
R147 "CRCW04020000Z0ED" 0402 1276,2331 r180 bottom
R148 "Resistor" 0402L 2062,315 r270 bottom
R149 "Resistor" 0402L 2098,314 r270 bottom
R150 "CRCW0402100RFKED" 0402 2381.32,514.32 r0 bottom
R151 "CRCW0402330KFKED" 0402L 127.65,961.04 r180 bottom
R152 "ERJ-2GE0R00X" 0402L 814,1071.5 r0 top
R153 "CRCW0402330KFKED" 0402L 127.65,917.74 r0 bottom
R154 "ERJ-2GEJ101X" 0402L 796,936 r270 top
R155 "CRCW040210K0FKED" 0402L 692.78,861.15 r90 bottom
R156 "CRCW20100000Z0EF" 2010 2752,628.3 r180 bottom
R157 "CRCW04020000Z0ED" 0402 2663,460 r180 bottom
R158 "CRCW040210K0FKED" 0402 2269,440 r270 bottom
R159 "Resistor" 0402L 2386,404 r90 bottom
R160 "ERJ-2GEJ511X" 0402L 13,480 r0 bottom
R161 "MCT06030Z0000ZP500" 0603 2000,54 r90 bottom
R162 "CRCW02010000Z0ED" 0201_Silk 1475,351 r180 top
R163 "CRCW02010000Z0ED" 0201_Silk 1377,366 r180 top
R164 "CRCW02010000Z0ED" 0201_Silk 1278,367 r180 top
R165 "CRCW02010000Z0ED" 0201_Silk 895,1612 r90 top
R166 "CRCW02010000Z0ED" 0201_Silk 832.75,169.28 r90 bottom
R167 "CRCW02010000Z0ED" 0201_Silk 2033.6,804.6 r180 top
R168 "CRCW02010000Z0ED" 0201_Silk 2039,928 r90 top
R169 "CRCW02010000Z0ED" 0201_Silk 685.13,169.28 r90 bottom
R170 "CRCW04022K94FKED" 0402 1473,441 r0 top
R171 "CRCW04022K94FKED" 0402 1473,393 r0 top
R172 "CRCW0402100KFKED" 0402L 874,162 r90 bottom
R173 "CRCW0402100KFKED" 0402L 759.88,161.15 r90 bottom
R174 "CRCW040230K0FKED" 0402L 2046,156 r90 bottom
R175 "MCT06030Z0000ZP500" 0603 1795,-7 r0 bottom
R177 "CRCW040210K0FKED" 0402L 1246.5,870.35 r270 top
R178 "ERJ-2GE0R00X" 0402L 1200.8,690.6 r270 top
R179 "CRCW020120R0FNED" 0201_033 811,2130.5 r270 top
R180 "CRCW020120R0FNED" 0201_033 778,2128 r270 top
R181 "CRCW020120R0FNED" 0201_033 753.5,2234.3 r270 top
R182 "CRCW020120R0FNED" 0201_033 745,2122 r270 top
R183 "CRCW020120R0FNED" 0201_033 721,2234.7 r270 top
R184 "CRCW020120R0FNED" 0201_033 712,2130 r270 top
R186 "CRCW040210K0JNED" 0402 1752,516 r0 bottom
R188 "Resistor" 0402L 1622,541 r180 bottom
R189 "Resistor" 0402L 1724,582 r180 bottom
R190 "CRCW040210K0JNED" 0402 1724,629 r0 bottom
R193 "CRCW040226K1FKED" 0402 544.7,1010.32 r270 top
R194 "CRCW040210K0FKED" 0402L 544.7,1099.34 r270 top
R196 "ERJ-2GE0R00X" 0402L 2098,858 r270 top
R197 "CRCW040210K0FKED" 0402L 177.8,1016.4 r270 top
R198 "CRCW02010000Z0ED" 0201_Silk 303.6,1075.8 r180 top
R199 "CRCW02010000Z0ED" 0201_Silk 300.3,934.8 r270 top
R200 "ERJ-2GE0R00X" 0402L 222.7,916.3 r270 top
R201 "CRCW02010000Z0ED" 0201_Silk 184.9,924.2 r270 top
R202 "ERJ-2GEJ361X" 0402L 45,780 r90 bottom
R208 "CRCW040210K0FKED" 0402L 1269,1253 r90 top
S1 "219-3MST" SW_219-3MST 596,205 r180 top
S2 "CJS-1201TA" SW_CJS_1201A 1424,1177 r180 top
SW1 "KMR243GLFG" SW_KMR243GLFG 336.65,1431.62 r180 top
SW2 "KMR243GLFG" SW_KMR243GLFG 335.7,1256 r180 top
TP1 "5001" Keystone5001 -5,224 r0 top
TP2 "TP_H0.45P0.75" TP_H045P075 1597.88,1231.78 r90 bottom
TP3 "5001" Keystone5001 984.57,-164.22 r90 bottom
U1 "MX25V1635FZNQ" WSON-8L_6x5MM_EP 1875.13,1947.18 r0 top
U2 "AWR1843ABL" ABL0161B 2294.55,1477.9 r180 top locked
U3 "TCAN1042HGVDQ1" D0008A_L 1116.31,902.98 r270 top
U4 "LP87702DRHBRQ1" RHB0032N 2171.27,651.27 r90 bottom
U5 "TPS7A5301QRGRRQ1" RGR0020A 1541.04,1134 r270 bottom
U6 "TM4C1294NCPDTT3" PDT0128A 511.79,1248.04 r0 bottom
U7 "LM4040C25QDBZR" DBZ0003A_N 8.08,1177.09 r180 bottom
U8 "LMS36x5" RNL0022A_NV 2535,177.72 r0 bottom
U10 "TPD4E004DRYR" DRY0006A 1976,276.76 r270 top
U11 "TPS79601DRBR" DRB0008B 436.9,1034.5 r0 top
U12 "TMP112AIDRLR" DRL0006A 1972.5,876.9 r0 top
U13 "TMP112AIDRLR" DRL0006A 240,1005.4 r270 top
U14 "TS3A5018RSVR" RSV0016A 1103,1268 r270 top
Y1 "CX3225SA40000D0PTWCC" KYOCERA_CX3225SA 1928,1281 r0 top
Y2 "NX3225SA-16.000M-STD-CRS-2" NDK_NX3225SA 973.46,1070.04 r270 bottom
ZZ1 "This Assembly Note is for PCB labels only" AssemblyNoteLabel -117.91,3554.91 r0 top
ZZ2 "These assemblies are ESD sensitive, ESD precautions shall be observed." AssemblyNote -118.31,3480.14 r0 top
ZZ3 "These assemblies must be clean and free from flux and all contaminants. Use of no clean flux is not acceptable." AssemblyNote -117.52,3404.58 r0 top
